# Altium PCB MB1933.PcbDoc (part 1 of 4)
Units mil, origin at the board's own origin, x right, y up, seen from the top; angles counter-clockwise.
Board outline 2755.91 x 3937.01 mil, 4 copper layers (Top Layer, GND, POWER, Bottom Layer), stack 60.63 mil thick; 228 components, 185 nets, 918 pads, 786 vias.
Unrouted connection lines stored in the file: 160.
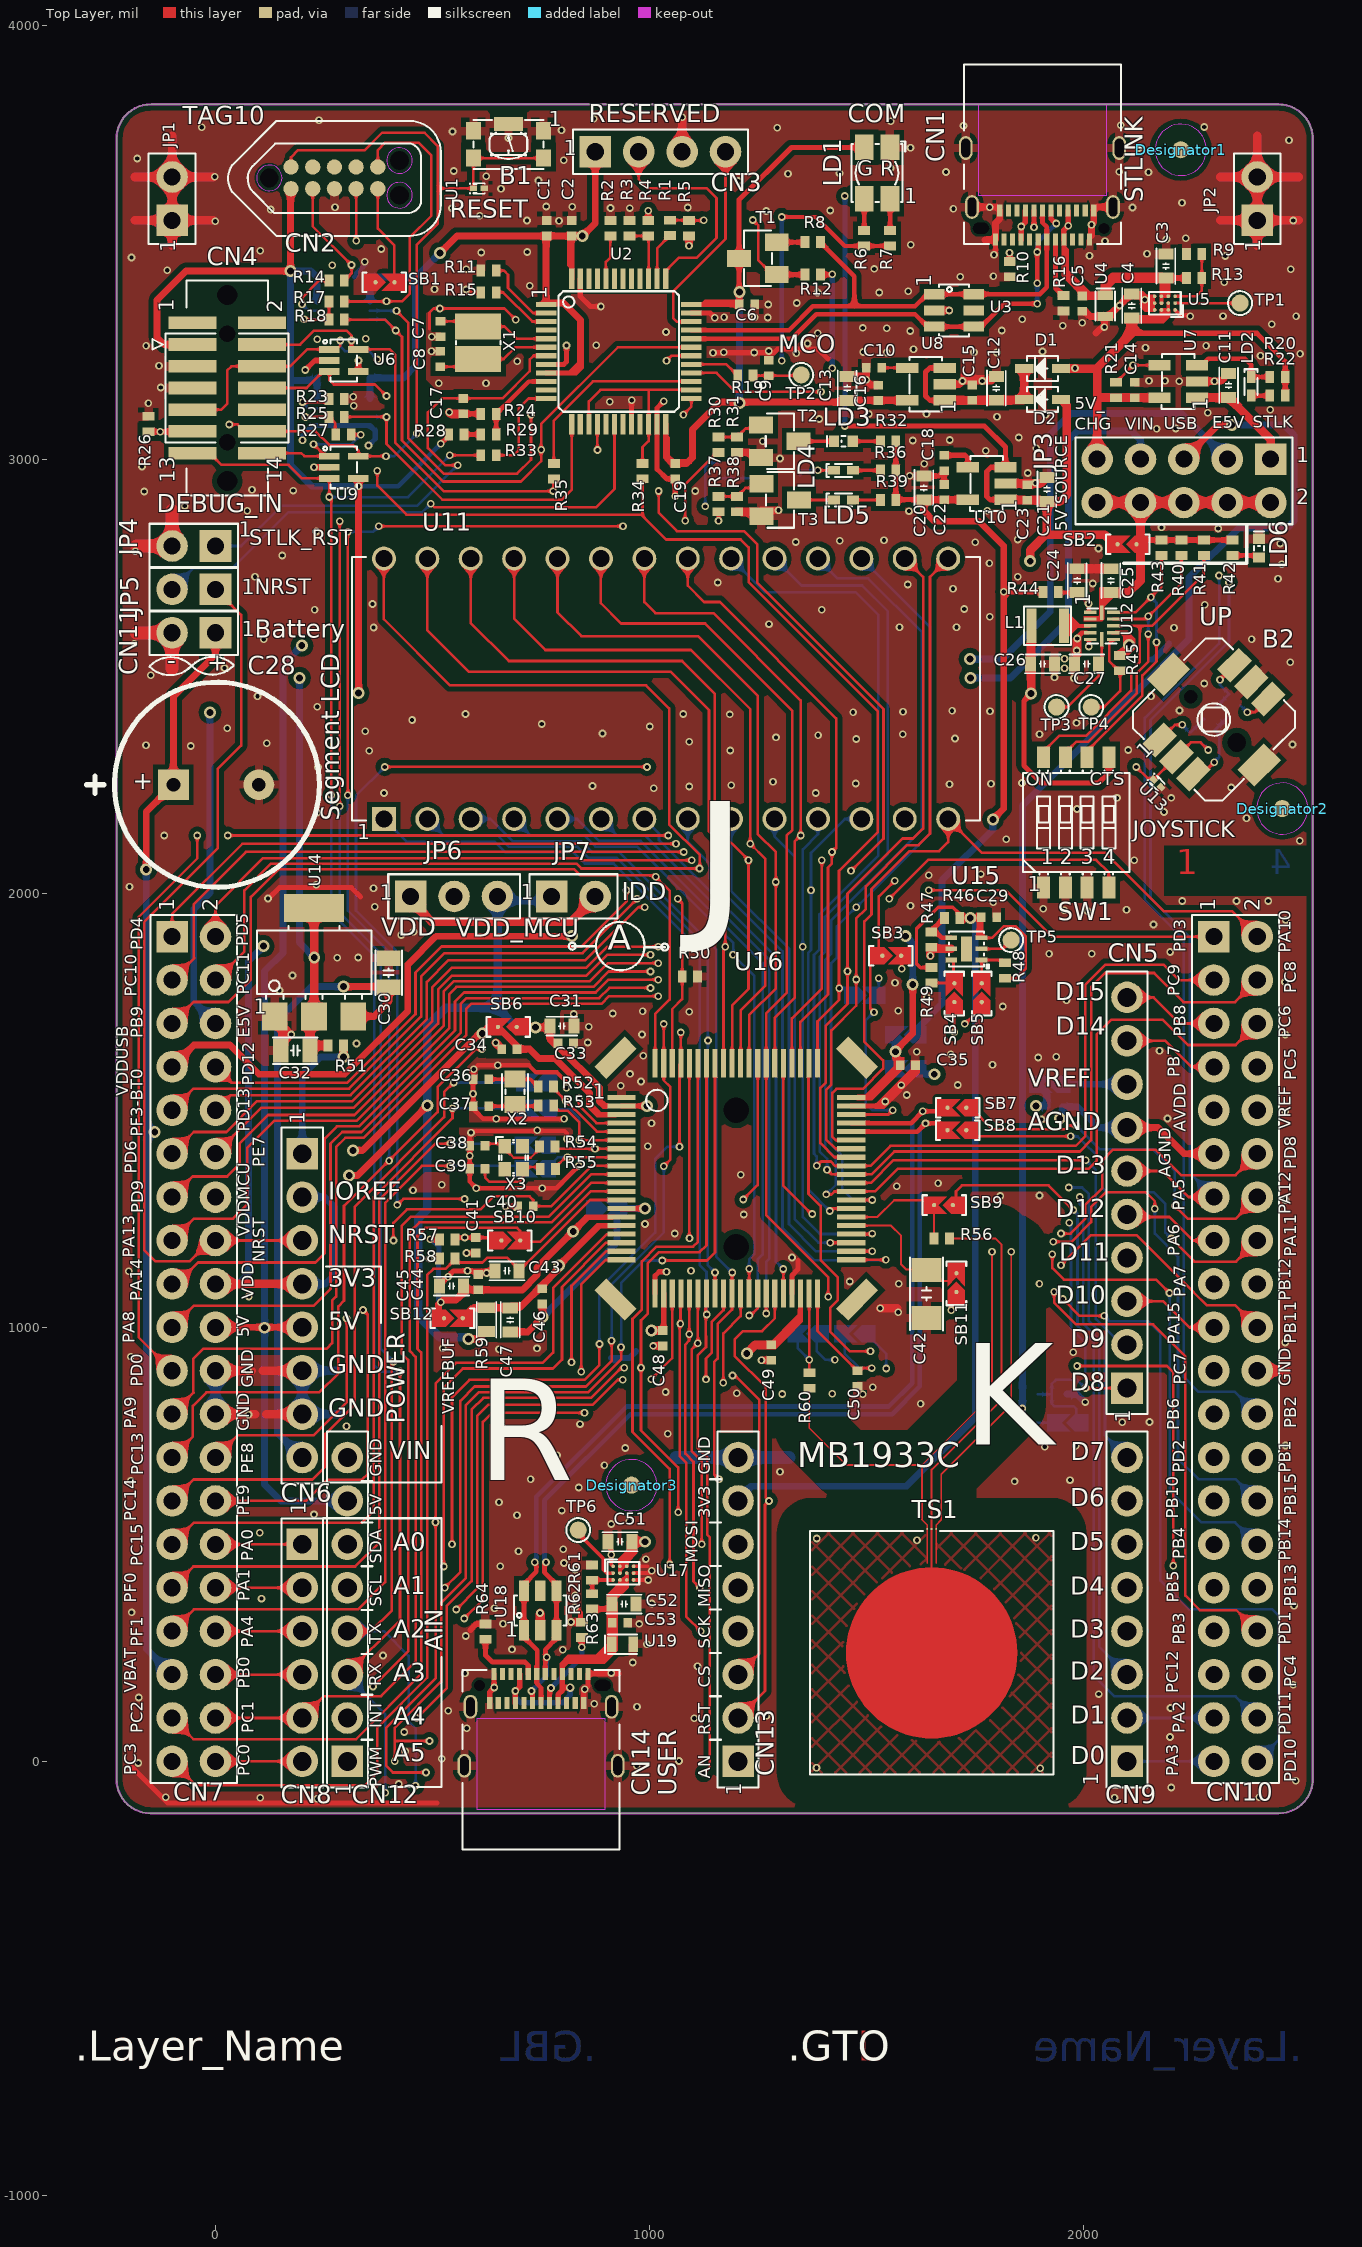
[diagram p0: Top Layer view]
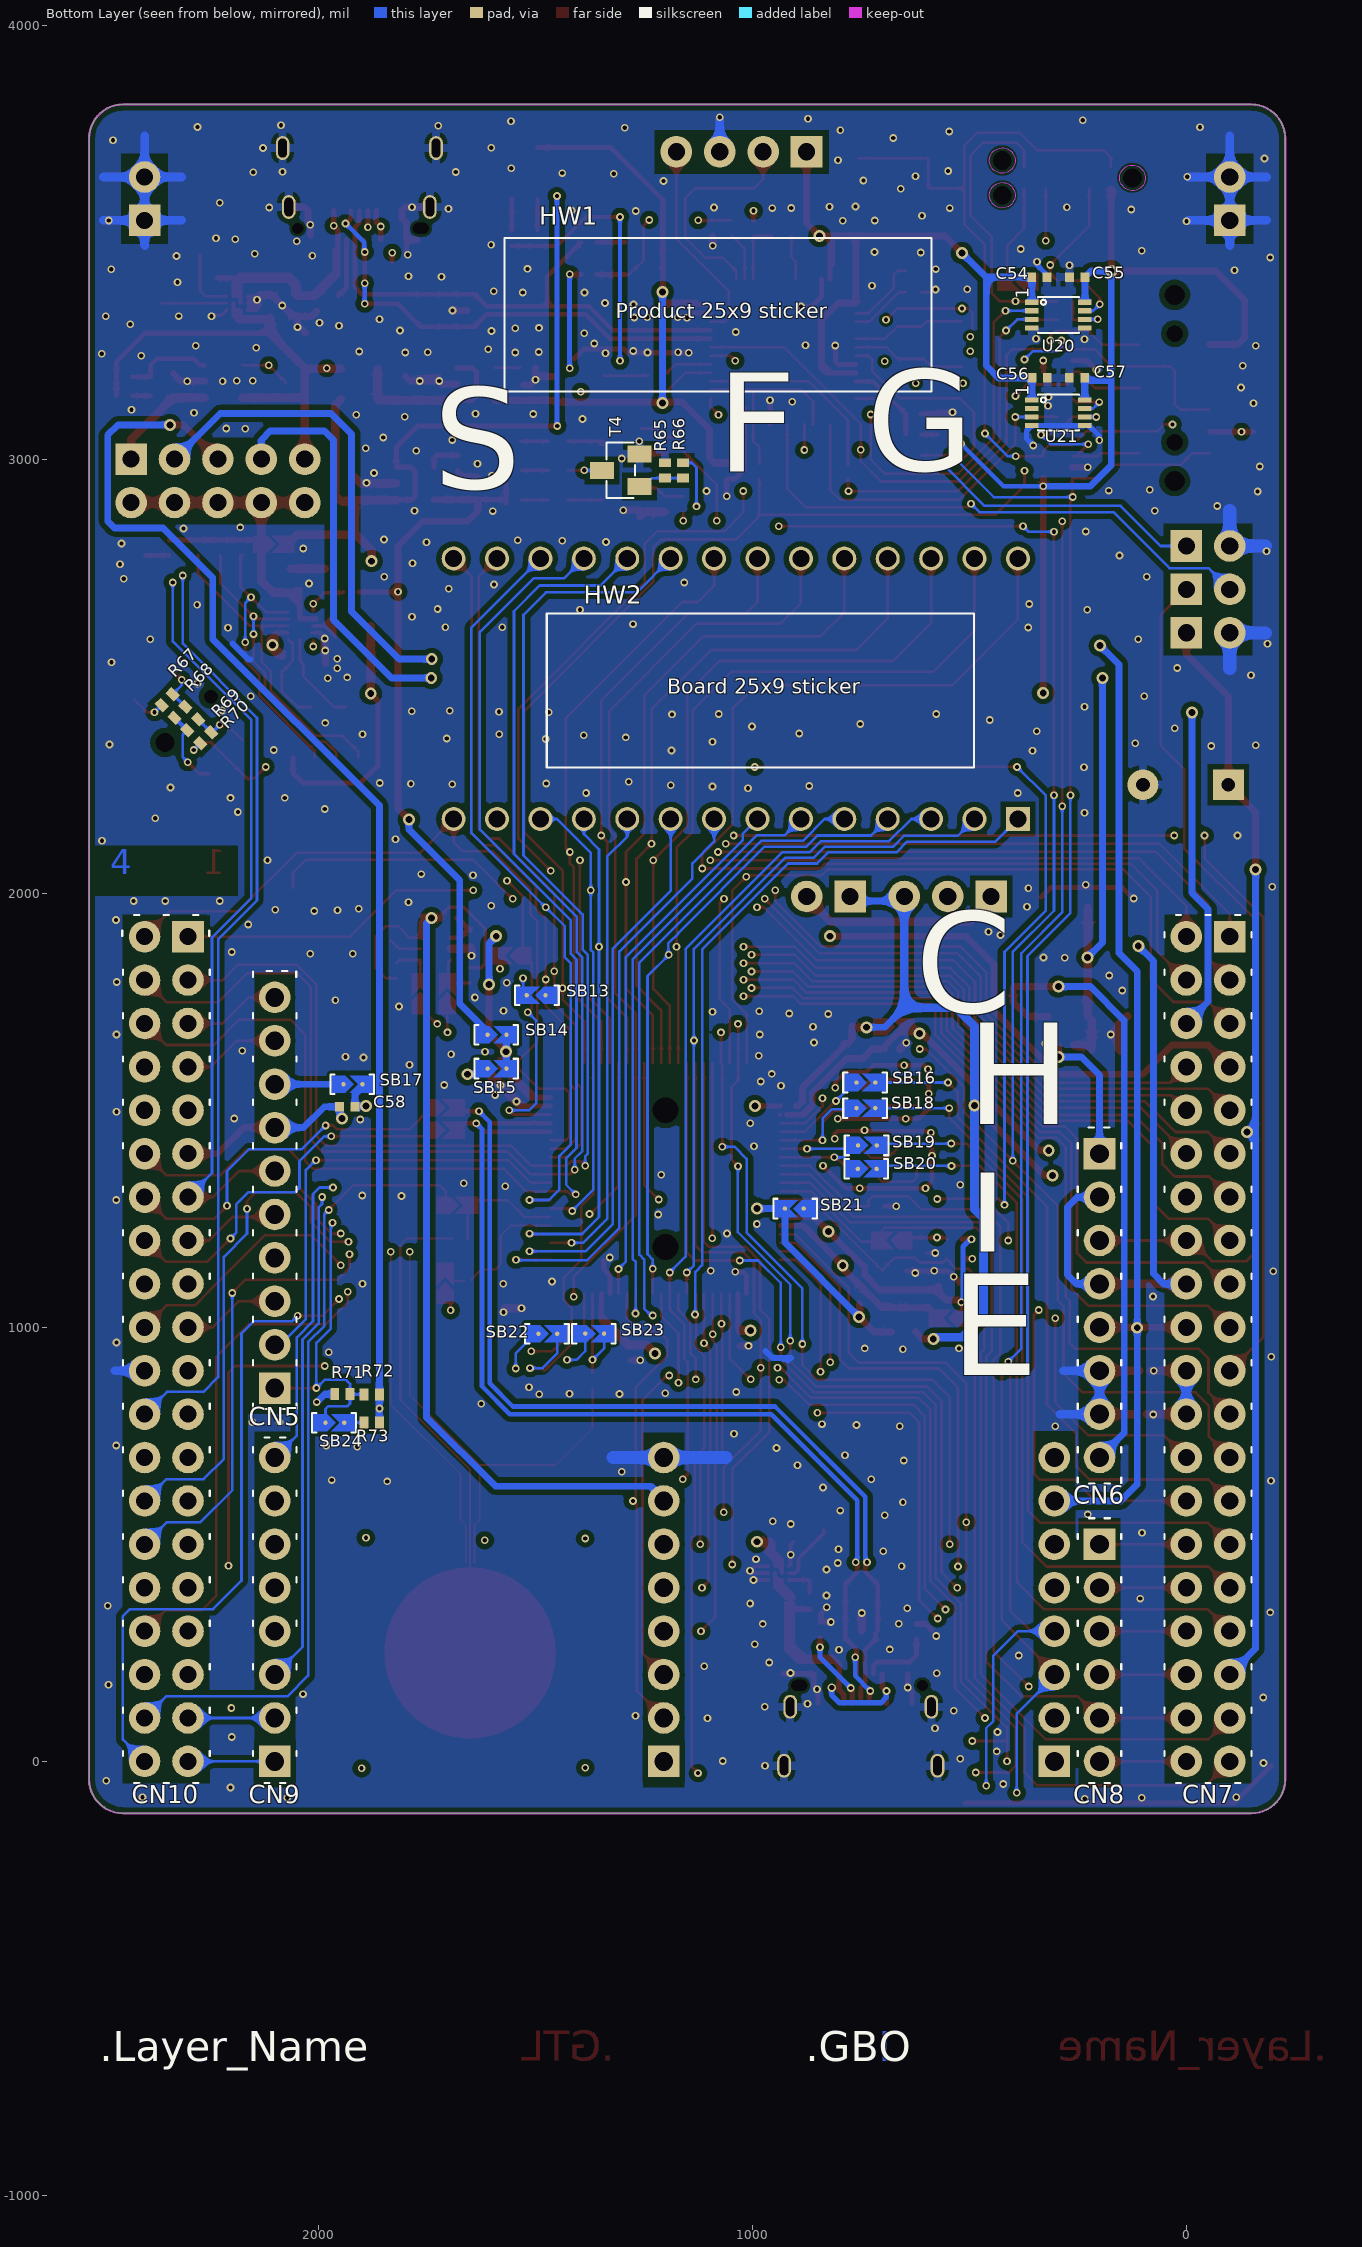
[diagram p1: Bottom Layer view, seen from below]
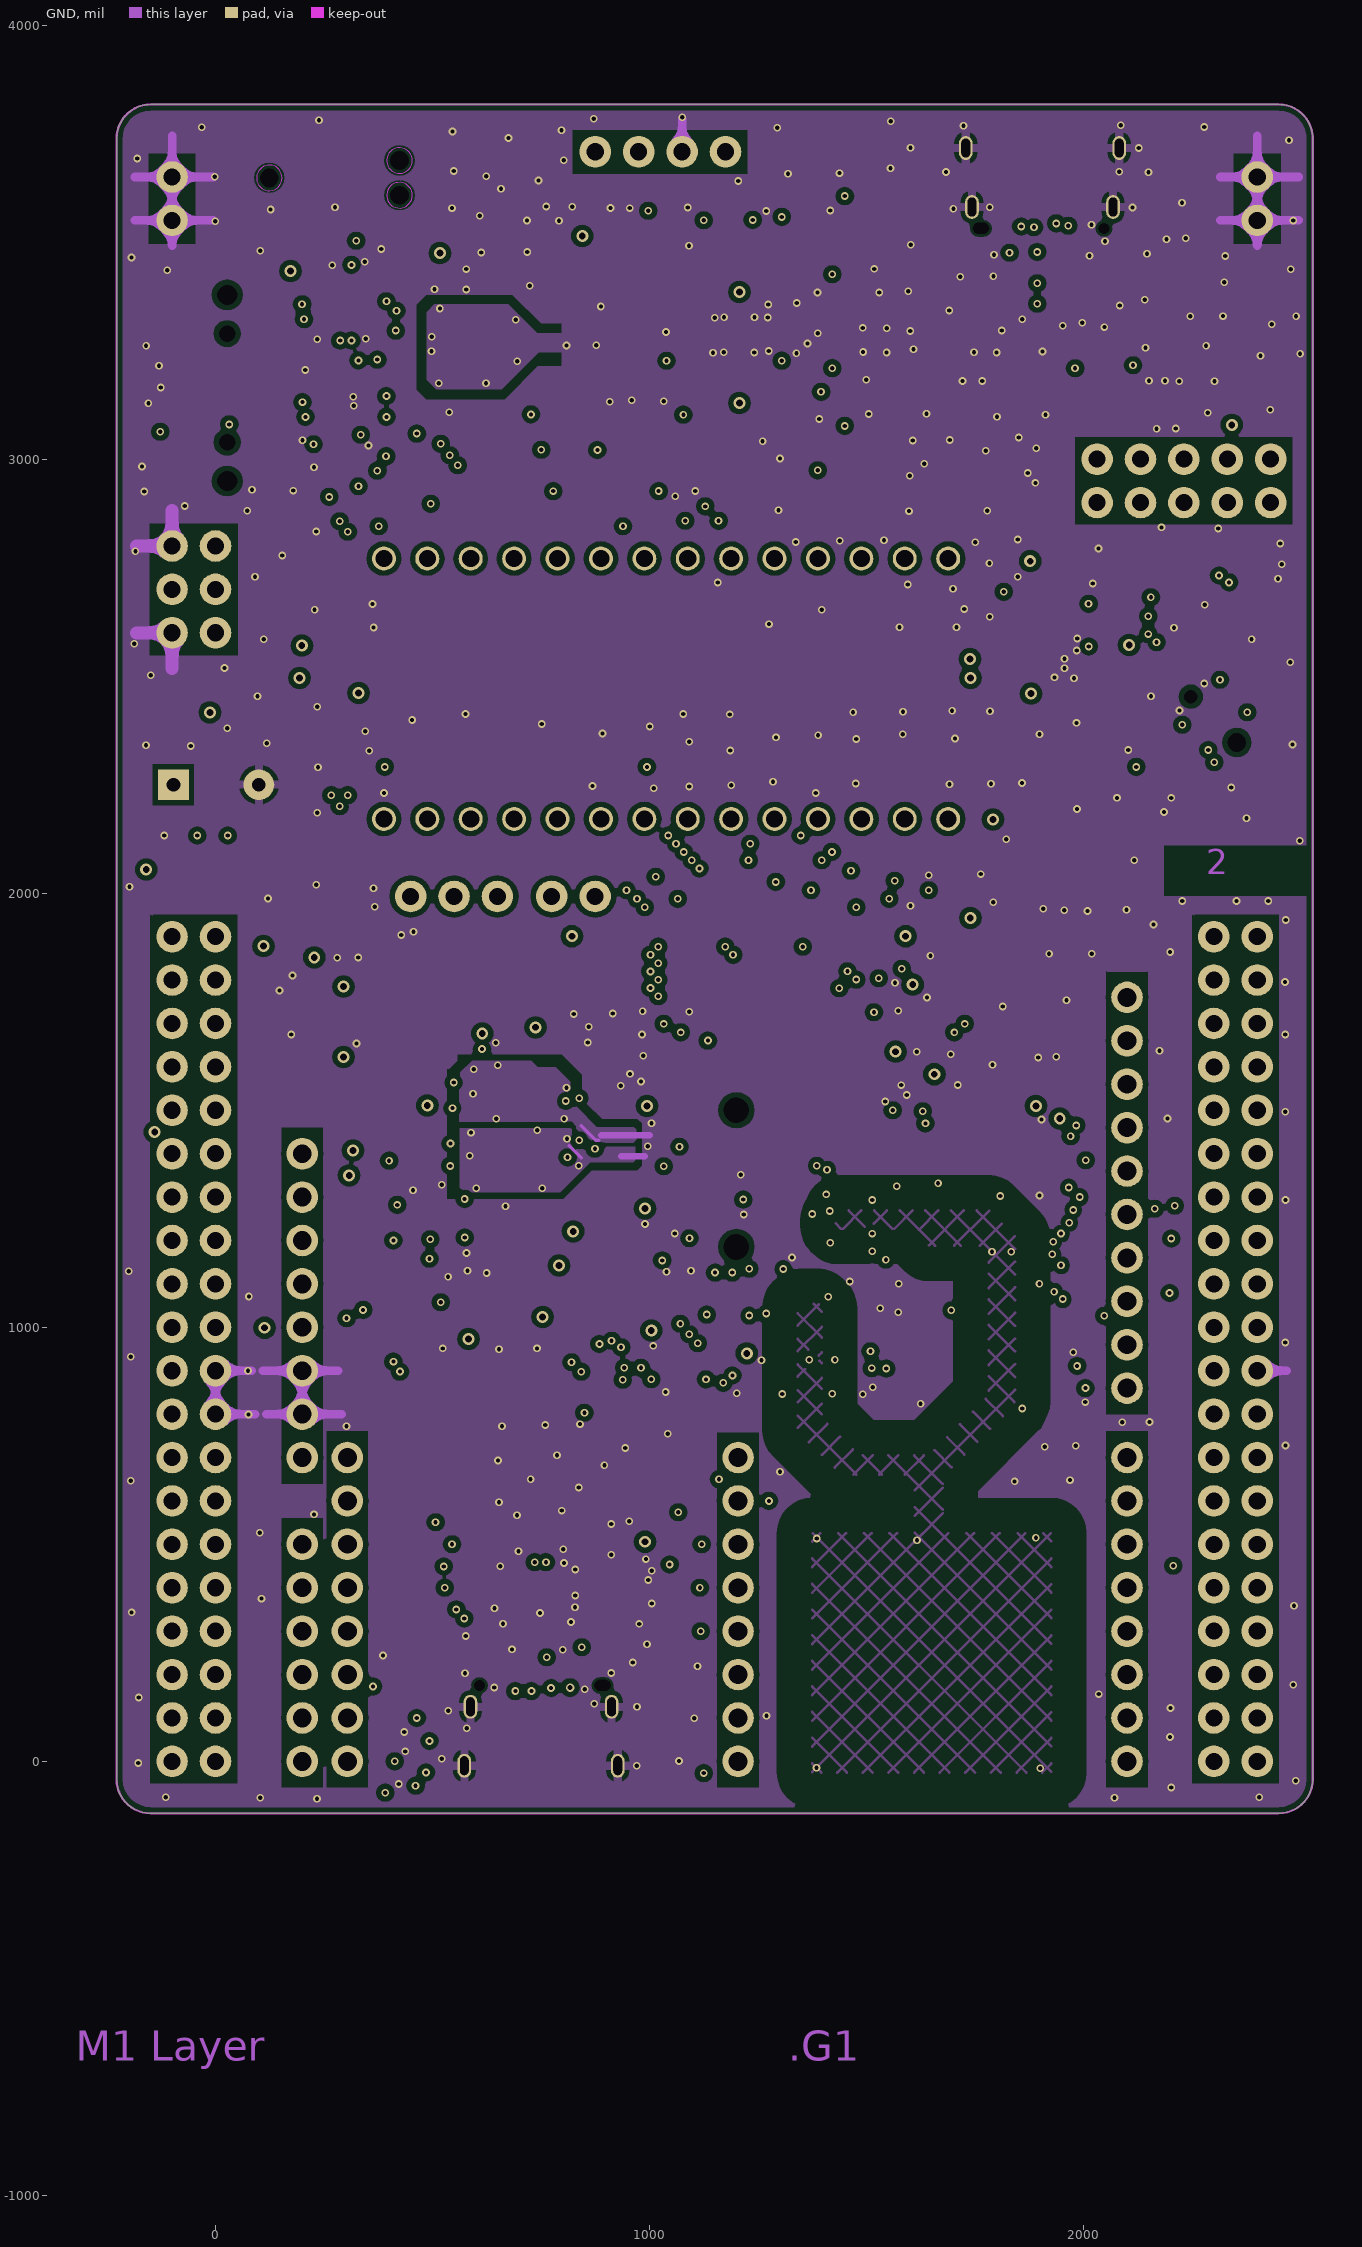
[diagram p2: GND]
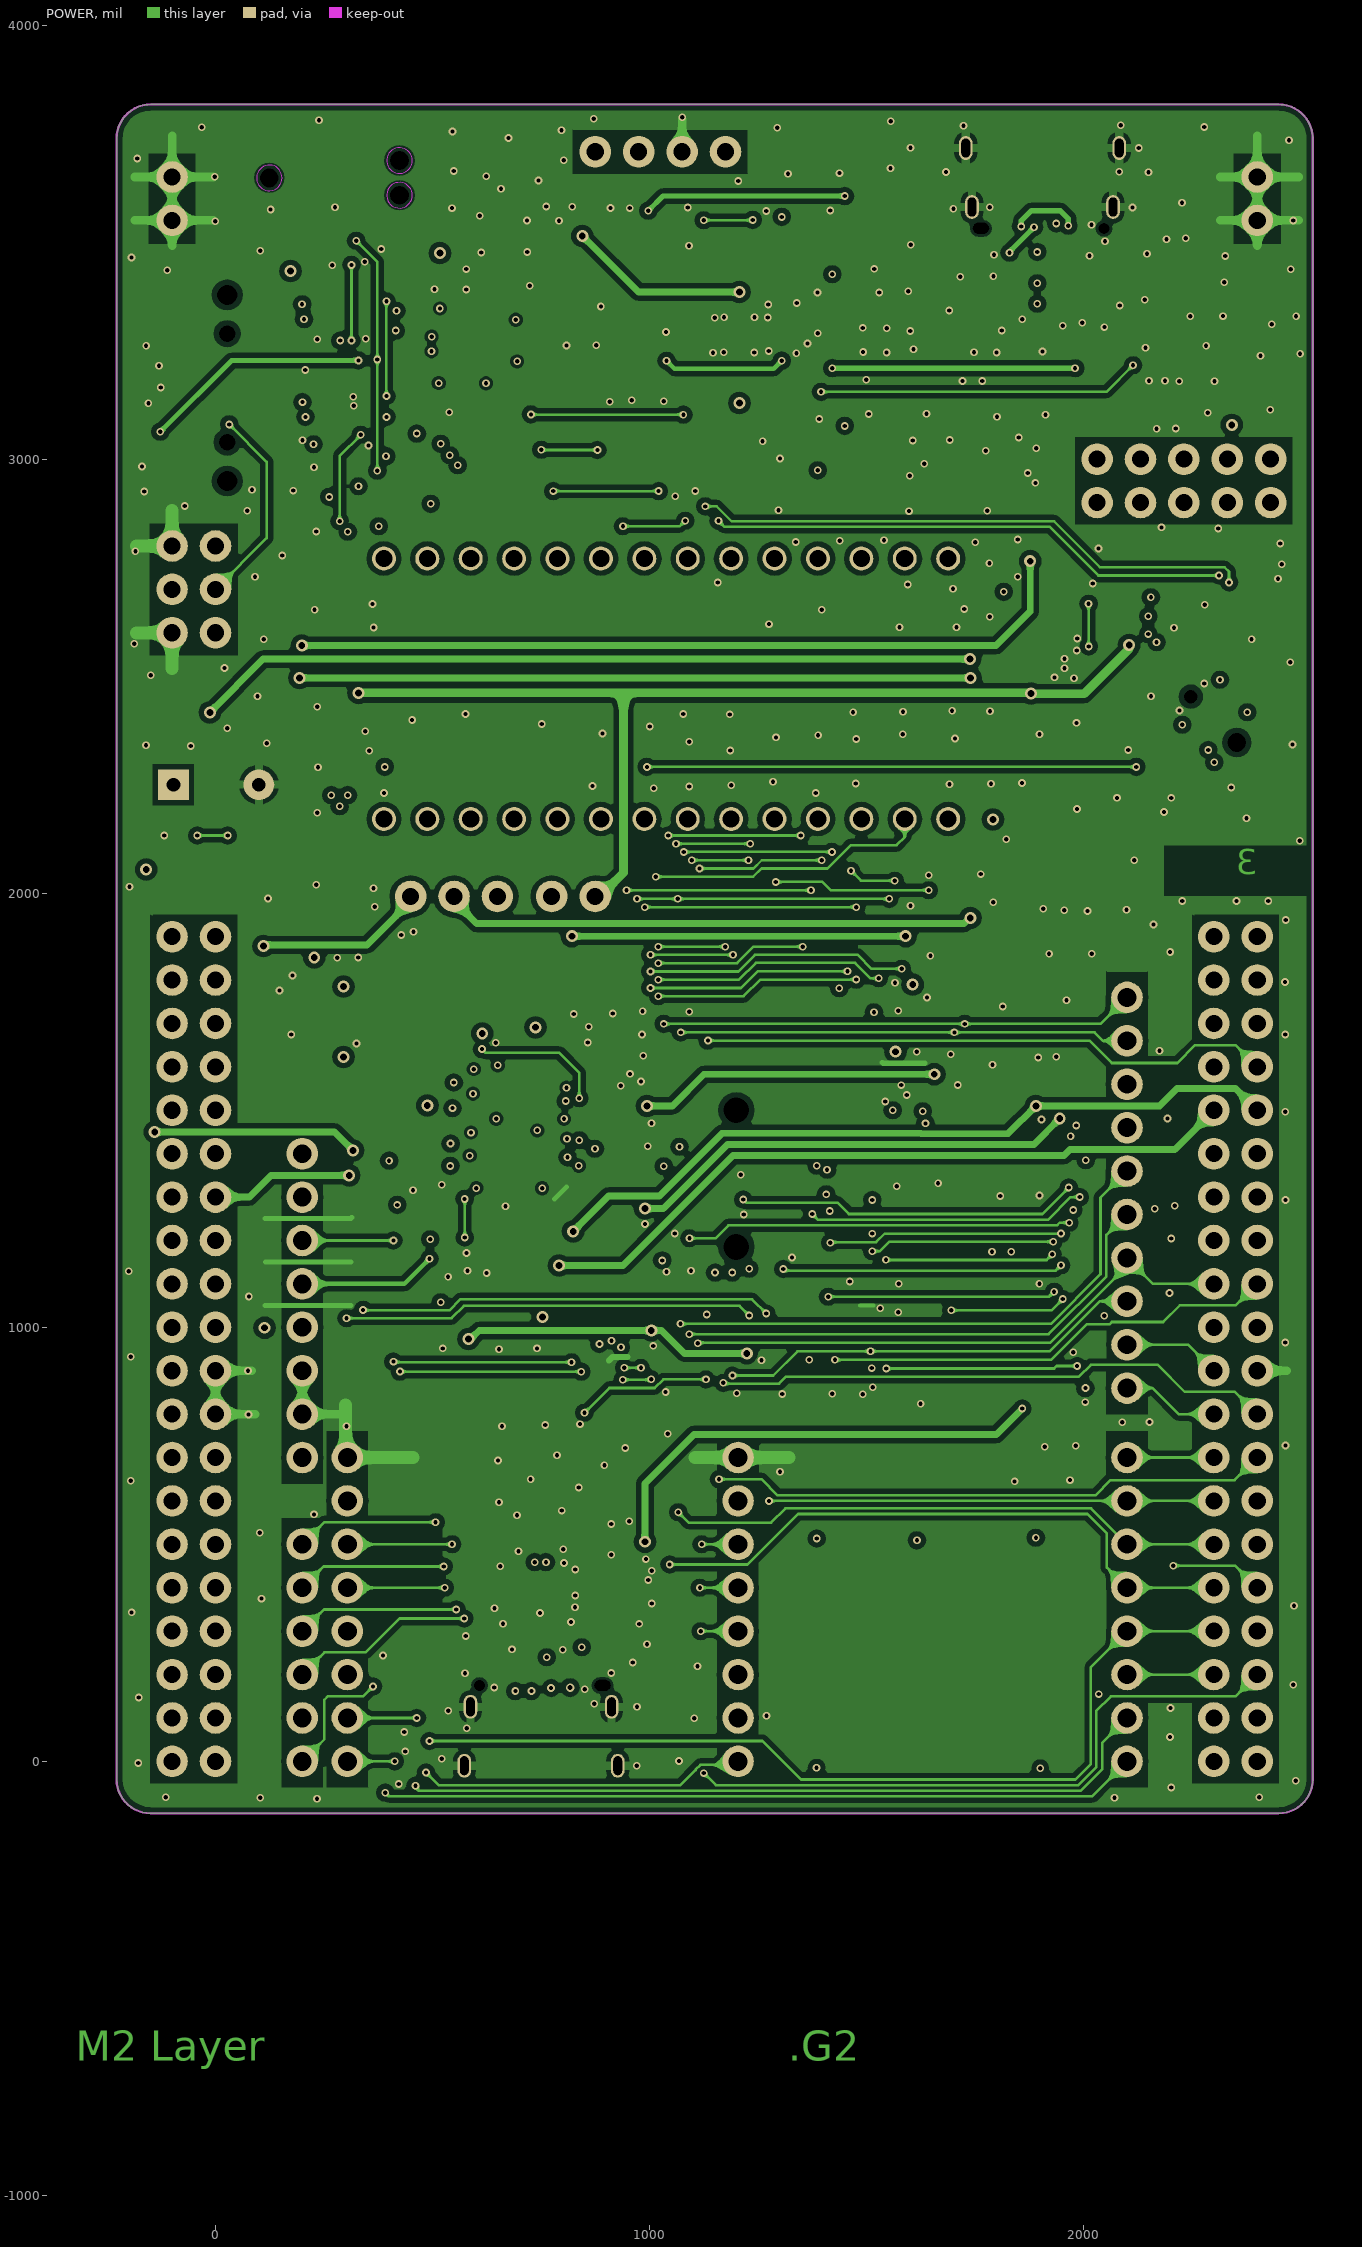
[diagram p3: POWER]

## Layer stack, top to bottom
Top Solder: solder mask 0.5909, Solder Resist, Dk 3.5
Top Layer: signal copper 1.378
Dielectric 1: core 7.874, FR-4, Dk 4.2
GND: signal copper 1.378
Dielectric 3: prepreg 39.3701, Dk 4.2
POWER: signal copper 1.378
Dielectric 2: core 7.874, Dk 4.2
Bottom Layer: signal copper 1.378
Bottom Solder: solder mask 0.5909, Solder Resist, Dk 3.5

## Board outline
-227.95,-41.01 ccw(c-149.21,-41.01) -149.21,-119.75 1681.5,-119.75 2449.22,-119.75 ccw(c2449.22,-41.01) 2527.96,-41.01 2527.96,3738.52 ccw(c2449.22,3738.52) 2449.22,3817.26 -149.21,3817.26 ccw(c-149.21,3738.52) -227.95,3738.52 -227.95,2084.98 -227.95,2084

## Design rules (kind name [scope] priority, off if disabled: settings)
Clearance CN1&CN14&U12 [InComponent('CN1')OR InComponent('CN14') OR InComponent('U12')] p1: gap=5.91 ignorepadtopadclearanceinfootprint=FALSE
Clearance Clearance_4 [InNamedPolygon('TS_SHIELD_1') vs InNet('TS_PAD')] p2: gap=5.91 ignorepadtopadclearanceinfootprint=FALSE
Clearance Clearance_3 [InNet('TS_PAD')OR InNet('TS_SHIELD') vs OnLayer('Top Layer') OR OnLayer('GND')] p3: gap=78.74 ignorepadtopadclearanceinfootprint=FALSE
Clearance CN2 [InComponent('CN2')] p4: gap=4.72 ignorepadtopadclearanceinfootprint=FALSE
Clearance Clearance_2 [InPolygon] p5: gap=11.81 ignorepadtopadclearanceinfootprint=FALSE
Clearance Clearance_1 [InNet('E5V') OR InNet('5V') OR InNet('AGND')OR InNet('VREF')  OR InNet('AVDD') OR InNet('5V_USB')  OR InNet('VDDUSB')OR InNet('VDD') OR InNet('VBAT') OR InNet('VDD_MCU') OR InNet('5V_USB') vs InComponent('CN10')OR InComponent('CN9')OR InComponent('CN5') OR InComponent('CN11') OR InComponent('CN7')OR InComponent('CN6') OR InComponent('JP4')  OR InComponent('CN14')] p6: gap=5.71 ignorepadtopadclearanceinfootprint=FALSE
Clearance KEEPOUT [OnLayer('M1-Board Shape') OR OnLayer('Keep-Out Layer')] p7: gap=15.75 ignorepadtopadclearanceinfootprint=FALSE
Clearance SB [(HasFootprint('SOLDER-BRIDGE_R0603-0R'))] p8: gap=6 ignorepadtopadclearanceinfootprint=FALSE
Clearance USB [InDifferentialPair('STLK_USB')OR InDifferentialPair('USB_CN')] p9: gap=7.87 ignorepadtopadclearanceinfootprint=FALSE
Clearance VIA&VIA [IsVia vs ISVIA] p10: gap=7.87 ignorepadtopadclearanceinfootprint=FALSE
Clearance X3 [(HasFootprint('CRY_NX1612SA_4P'))] p11: gap=5 ignorepadtopadclearanceinfootprint=FALSE
Clearance [All] p12: gap=7 ignorepadtopadclearanceinfootprint=FALSE
ComponentClearance [All] p1: gap=7.87 collisioncheckmode=3 verticalgap=7.87 showdistances=FALSE
DiffPairsRouting [All] p1: maxlimit=20 minlimit=7.87 mostfreqgap=7.87 toplayer_minwidth=10.63 toplayer_maxwidth=10.63 toplayer_prefwidth=10.63 midlayer1_minwidth=10.63 midlayer1_maxwidth=10.63 midlayer1_prefwidth=10.63 midlayer2_minwidth=10.63 midlayer2_maxwidth=10.63 midlayer2_prefwidth=10.63 bottomlayer_minwidth=10.63 bottomlayer_maxwidth=10.63 bottomlayer_prefwidth=10.63 maxuncoupledlength=500
HoleSize [All] p1: absolutevalues=TRUE maxlimit=150 minlimit=1 maxpercent=80.000 minpercent=20.000
MaxMinImpedance "Schematic Impedance Constraint_5" [InNet('PA11')] p1: minimum=85.00 maximum=95.00
MaxMinImpedance "Schematic Impedance Constraint_4" [InNet('PA12')] p2: minimum=85.00 maximum=95.00
MaxMinImpedance "Schematic Impedance Constraint_2" [InNet('STLK_USB_P')] p3: minimum=85.00 maximum=95.00
MaxMinImpedance "Schematic Impedance Constraint_1" [InNet('STLK_USB_N')] p4: minimum=85.00 maximum=95.00
MinimumSolderMaskSliver [All] p1: minsoldermaskwidth=0
PolygonConnect VIA [IsVia] p1: connectstyle=Direct reliefconductorwidth=10 reliefentries=4 polygonreliefangle="90 Angle" airgapwidth=10
PolygonConnect [All] p2: connectstyle=Relief reliefconductorwidth=19.68 reliefentries=4 polygonreliefangle="90 Angle" airgapwidth=10
RoutingVias [All] p1: holewidth=8 width=15 viastyle="Through Hole" minholewidth=8 minwidth=15 maxholewidth=28 maxwidth=50
SilkToSilkClearance [All] p1: silktosilkclearance=4
SilkToSolderMaskClearance [IsPad] p1: minsilkscreentomaskgap=0.5 clearancetoexposedcopper=TRUE
SolderMaskExpansion [All] p1: expansion=4 istentingtop=FALSE
Width [All] p1: maxlimit=30 minlimit=3 preferedwidth=8
24 further rules are at their usual default settings.

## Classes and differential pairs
component class U_USB-C_Device: C51 C52 C53 CN14 R61 R62 R63 R64 R71 R72 R73 SB24 TP6 U17 U18 U19
component class U_STM32_microcontroller_power: C28 C31 C33 C34 C35 C44 C45 C46 C47 C48 C49 CN11 R59 SB6 SB12 SB14 SB15 SB21
component class U_Segment_LCD: HW9 U11
component class U_PERIPHERAL: B2 C29 C41 C42 C50 HW10 HW11 JP6 LD3 LD4 LD5 R30 R31 R32 R36 R37 R38 R39 R46 R47 R48 R49 R56 R57 R60 R65 R66 R67 R68 R69 R70 SB10 T2 T3 T4 TP5 TS1 U13 U15
component class U_HW_Mechanical_Parts: HW1 HW2 HW3
component class U_STLINK_V2EC: C1 C2 C3 C4 C5 C6 C7 C8 C9 C10 C11 C12 C13 C14 C15 C16 C17 C19 C54 C55 C56 C57 CN1 CN2 CN3 CN4 D1 D2 JP4 JP5 LD1 LD2 R1 R2 R3 R4 R5 R6 R7 R8 R9 R10 R11 R12 R13 R14 R15 R16 R17 R18 R19 R20 R21 R22 R23 R24 R25 R26 R27 R28 R29 R33 R34 R35 SB1 T1 TP1 TP2 U2 U3 U4 U5 U6 U7 U8 U9 U20 U21 X1
component class U_Arduino_Mikrobus_connectors: C58 CN5 CN6 CN8 CN9 CN12 CN13 JP1 JP2 R51 SB17
component class U_STM32_microcontroller_IOs: B1 C36 C37 C38 C39 C40 C43 CN7 CN10 HW6 HW7 HW8 HW9 R50 R52 R53 R54 R55 R58 SB3 SB4 SB5 SB7 SB8 SB9 SB11 SB13 SB16 SB18 SB19 SB20 SB22 SB23 U1 U16 X2 X3
component class U_Power: C18 C20 C21 C22 C23 C24 C25 C26 C27 C30 C32 HW12 HW13 JP3 JP7 L1 LD6 R40 R41 R42 R43 R44 R45 SB2 SW1 TP3 TP4 U10 U12 U14
differential pair STLK_USB: +STLK_USB_P -STLK_USB_N

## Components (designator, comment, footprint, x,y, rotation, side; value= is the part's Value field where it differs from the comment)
B1 "SW-PUSH-CMS_KMR2_BLACK" SWI_C&K_Y78B23110FP__ITT_KMR231GLFS 675,3725 r0 top locked value=KMR231GLFS
B2 "Joystick MT-008A_M" SWI_XIEJIA_MT-008A_6P 2300,2400 r45 top locked value=MT-008A
C1 "Capacitor" C0402 762.8,3532 r90 top value=100nF
C2 "Capacitor" C0402 821,3532 r90 top value=100nF
C3 "Capacitor" C0603 2189.73,3444.75 r90 top value=100nF
C4 "Capacitor" C0603 2110.81,3353.25 r270 top value=10uF
C5 "Capacitor" C0402 1996.96,3358.25 r270 top value=100pF
C6 "Capacitor" C0402 1224.61,3356.44 r0 top value=100nF
C7 "Capacitor" C0402 518.41,3299.84 r90 top value=10pF
C8 "Capacitor" C0402 517.82,3230.75 r90 top value=10pF
C9 "Capacitor" C0402 1274.71,3209.98 r270 top value=20pF
C10 "Capacitor" C0402 1516.98,3210.57 r0 top value=10nF
C11 "Capacitor" C0603 2333.81,3169.92 r270 top value=10uF
C12 "Capacitor" C0603 1798.96,3163.32 r270 top value=1uF
C13 "Capacitor" C0603 1455.16,3163.13 r270 top value=1uF
C14 "Capacitor" C0402 2117.86,3159.39 r270 top value=100nF
C15 "Capacitor" C0402 1743.55,3153.29 r270 top value=100nF
C16 "Capacitor" C0402 1526.72,3152.89 r270 top value=100nF
C17 "Capacitor" C0402 571.17,3122.18 r90 top value=100nF
C18 "Capacitor" C0402 1678.55,2991.18 r90 top value=10nF
C19 "Capacitor" C0402 1058.96,2972.25 r270 top value=100nF
C20 "Capacitor" C0603 1632,2933.6 r270 top value=1uF
C21 "Capacitor" C0603 1915.56,2930.35 r270 top value=1uF
C22 "Capacitor" C0402 1678.53,2924.08 r270 top value=100nF
C23 "Capacitor" C0402 1870.58,2923.17 r270 top value=100nF
C24 "Capacitor" C0603 1985,2720 r270 top value=10uF
C25 "Capacitor" C0603 2063,2720 r270 top value=10uF
C26 "Capacitor" C0603 1905.27,2528.25 r180 top value=10uF
C27 "Capacitor" C0603 2006.96,2528.25 r0 top value=10uF
C28 "Cap_POL_TANA" CPOL_TDK_B41888C5477M000_H16 -96.85,2250 r0 top locked value=470uF
C29 "Capacitor" C0402 1782,1945 r180 top value=100nF
C30 "Capacitor" C0805 398.83,1816.87 r270 top value=10uF
C31 "Capacitor" C0603_H0P8 798,1694 r180 top value=4.7uF
C32 "Capacitor" C0805 184.26,1637.54 r0 top value=10uF
C33 "Capacitor" C0402 807,1654 r180 top value=100nF
C34 "Capacitor" C0402 677,1641 r0 top value=100nF
C35 "Capacitor" C0402 1595,1604 r180 top value=100nF
C36 "Capacitor" C0402 611.62,1571.69 r0 top value=8.2pF
C37 "Capacitor" C0402 611.62,1509.58 r0 top value=8.2pF
C38 "Capacitor" C0402 603.45,1418 r0 top value=5.6pF
C39 "Capacitor" C0402 603.45,1365 r0 top value=5.6pF
C40 "Capacitor" C0402 714.28,1279.07 r0 top value=100nF
C41 "Capacitor" C0402 599.32,1189.11 r90 top value=10nF
C42 "Capacitor" C1206_H0P85 1638,1077 r270 top value=39nF
C43 "Capacitor" C0603 671.76,1129.96 r0 top value=1uF
C44 "Capacitor" C0402 605.72,1103.97 r270 top value=100nF
C45 "Capacitor" C0603 543.7,1095.12 r180 top value=1uF
C46 "Capacitor" C0402 753.26,1071.4 r90 top value=100nF
C47 "Capacitor" C0603 679,1016.94 r270 top value=1uF
C48 "Capacitor" C0402 1030.5,974.9 r90 top value=100nF
C49 "Capacitor" C0402 1280,942 r90 top value=100nF
C50 "Capacitor" C0402 1479,882.02 r270 top value=390nF
C51 "Capacitor" C0603 932,506 r0 top value=10uF
C52 "Capacitor" C0603 941.44,362.5 r0 top value=100nF
C53 "Capacitor" C0402 931.77,319 r0 top value=100pF
C54 "Capacitor" C0402 338.49,3419.35 r0 bottom value=100nF
C55 "Capacitor" C0402 251.29,3419.35 r0 bottom value=100nF
C56 "Capacitor" C0402 337.96,3187.34 r0 bottom value=100nF
C57 "Capacitor" C0402 251.96,3187.34 r0 bottom value=100nF
C58 "Capacitor" C0402 1933,1508 r180 bottom value=100nF
CN1 "USB_TYPE_C_Receptacle" CON_USB-TYPEC_AMPHENOL_12401826E412A 1905.27,3531.73 r180 top locked value=USB_C_12401826E412A
CN2 "Tag-10-C" CON_TAG-C_TC2050-IDC-NL 274,3648 r0 top locked value="Header 5x2"
CN3 "Header 4x1" CON_SAMTEC_TSW-104-07-G-S 1024.96,3708.25 r0 top locked
CN4 "Header 7x2" CON_STDC14_Receiver_MEDIUM_WITH_MIPI10_3D 27,3164 r270 top locked value="Header 5x2"
CN5 "Socket 10x1" CON_SAMTEC_SSW-110-01-X-S 2100,1310 r90 top locked
CN6 "Socket 8x1" CON_SAMTEC_SSW-108-01-X-S 200,1050 r270 top locked
CN7 "Header 20x2" CON_SAMTEC_TSW-120-09-G-D -50,950 r270 top locked
CN8 "Socket 6x1" CON_SAMTEC_SSW-106-01-X-S 200,250 r270 top locked
CN9 "Socket 8x1" CON_SAMTEC_SSW-108-01-X-S 2100,350 r90 top locked
CN10 "Header 20x2" CON_SAMTEC_TSW-120-09-G-D 2350,950 r270 top locked
CN11 "Header 2x1" CON_SAMTEC_TSW-102-07-G-S -50,2600 r180 top
CN12 "Socket 8x1" CON_SAMTEC_SSW-108-01-X-S 303.94,350 r90 top
CN13 "Socket 8x1" CON_SAMTEC_SSW-108-01-X-S 1203.94,350 r90 top
CN14 "USB_TYPE_C_Receptacle" CON_USB-TYPEC_AMPHENOL_12401826E412A 750,175 r0 top locked value=USB_C_12401826E412A
D1 "BAT60JFILM" DIO_SOD323 1905.46,3208.73 r180 top
D2 "BAT60JFILM" DIO_SOD323 1905.46,3137.73 r180 top
Designator1 "Comment" MIRE_PLACE_SMD_1MM 2224,3712.8 r0 top
Designator2 "Comment" MIRE_PLACE_SMD_1MM 2457.49,2195.07 r0 top
Designator3 "Comment" MIRE_PLACE_SMD_1MM 958.58,636.33 r0 top
HW1 "STICKER_PRODUCT" STICKER_PRODUCT_25X9 1079.19,3332.65 r180 bottom locked value="Sticker product"
HW2 "STICKER_BOARD" STICKER_BOARD_25X9 981.4,2467.06 r180 bottom locked value="Sticker board"
JP1 "Jumper_Header 2x1" CON_SAMTEC_TSW-102-09-X-S -100,3600 r90 top value="Header 2x1"
JP2 "Jumper_Header 2x1" CON_SAMTEC_TSW-102-09-X-S 2400,3600 r90 top value="Header 2x1"
JP3 "Jumper_Header 5x2 Fitted 1-2" CON_SAMTEC_TSW-105-07-X-D 2231,2950 r180 top locked value="Header 5x2"
JP4 "Jumper_Header 2x1" CON_SAMTEC_TSW-102-07-G-S -50,2800 r180 top value="Header 2x1"
JP5 "Jumper_Header 2x1 Fitted" CON_SAMTEC_TSW-102-07-G-S -50,2700 r180 top value="Header 2x1"
JP6 "Jumper_Header 3x1 Fitted 1-2" CON_SAMTEC_TSW-103-07-F-S 549.58,1992.58 r0 top value="Header 3x1"
JP7 "Jumper_Header 2x1 Fitted" CON_SAMTEC_TSW-102-07-G-S 824.58,1992.58 r0 top value="Header 2x1"
L1 "Inductor" IND_TDK_VLS252010HBX-1 1917.13,2616.28 r180 top value=2.2uH
LD1 "LED_BICOLOR" LED_BI-GR_WE-150141SV73110 1524.15,3659.18 r180 top value=Green/Red
LD2 "LED_red" LED_0402_KINGBRIGHT_KPHHS-1005SURCK_HYPER-RED_1A2K_H0P5 2385.8,3167.81 r90 top value=Red
LD3 "LED_green" "LED_0402_EVERLIGHT_16-213SYGC/S530-E3-TR8 _YELLOW-GREEN_1A2K_H0P45" 1446.69,3041.28 r0 top value=Yellow/Green
LD4 "LED_blue" LED_0402_KINGBRIGHT_KPHHS-1005QBC-D-V_BLUE_1A2K_H0P5 1446.69,2974.16 r180 top value=Blue
LD5 "LED_red" LED_0402_KINGBRIGHT_KPHHS-1005SURCK_HYPER-RED_1A2K_H0P5 1446.69,2905.94 r180 top value=Red
LD6 "LED_green" "LED_0402_EVERLIGHT_16-213SYGC/S530-E3-TR8 _YELLOW-GREEN_1A2K_H0P45" 2404,2795.02 r270 top value=Yellow/Green
R1 "Resistor" R0402 1046.9,3532.86 r270 top value=100R
R2 "Resistor" R0402 909.75,3532.03 r270 top value=100K
R3 "Resistor" R0402 954,3532 r90 top value=10K
R4 "Resistor" R0402 997,3532 r90 top value=5K1
R5 "Resistor" R0402 1091,3532 r90 top value=36K
R6 "Resistor" R0402 1494.19,3508.93 r90 top value=330R
R7 "Resistor" R0402 1554.19,3508.93 r270 top value=1K
R8 "Resistor" R0402 1376,3500 r180 top value=1K5
R9 "Resistor" R0402 2254.59,3472.31 r0 top value=180K
R10 "Resistor" R0402 1829.83,3437.64 r270 top value=5K1
R11 "Resistor" R0402 629,3434.38 r180 top value=10K
R12 "Resistor" R0402 1376,3425 r0 top value=10K
R13 "Resistor" R0402 2254.59,3417.29 r180 top value=680K
R14 "Resistor" R0402 279.23,3411.25 r0 top value=33R
R15 "Resistor" R0402 629,3384.38 r180 top value=10K
R16 "Resistor" R0402 1953.31,3359.22 r270 top value=5K1
R17 "Resistor" R0402 279.23,3363.25 r0 top value=33R
R18 "Resistor" R0402 279.23,3321.34 r180 top value=0R
R19 "Resistor" R0402 1220.6,3192.55 r0 top value=100R
R20 "Resistor" R0402 2446.8,3189.49 r0 top value=100K
R21 "Resistor" R0402 2074.55,3159.39 r270 top value=100K
R22 "Resistor" R0402 2446.8,3146.49 r0 top value=1K
R23 "Resistor" R0402 279.23,3138.32 r0 top value=0R
R24 "Resistor" R0402 629,3104.3 r180 top value=10K
R25 "Resistor" R0402 279.23,3097.58 r180 top value=0R
R26 "Resistor" R0402 -154.42,3081.04 r270 top value=100R
R27 "Resistor" R0402 294.89,3057.22 r0 top value=33R
R28 "Resistor" R0402 555,3057 r180 top value=0R
R29 "Resistor" R0402 629,3056.65 r180 top value=10K
R30 "Resistor" R0402 1159.36,3033.3 r90 top value=47K
R31 "Resistor" R0402 1201.29,3033.3 r90 top value=100K
R32 "Resistor" R0402 1549.61,3041.28 r0 top value=270R
R33 "Resistor" R0402 629,3009 r180 top value=33R
R34 "Resistor" R0402 983.77,2972.28 r270 top value=33R
R35 "Resistor" R0402 779.41,2972.25 r270 top value=33R
R36 "Resistor" R0402 1549.61,2974.16 r0 top value=360R
R37 "Resistor" R0402 1159.35,2896.4 r90 top value=47K
R38 "Resistor" R0402 1201.28,2896.4 r90 top value=100K
R39 "Resistor" R0402 1549.61,2905.94 r0 top value=360R
R40 "Resistor" R0402 2225,2796 r270 top value=1M
R41 "Resistor" R0402 2277,2796 r270 top value=1M
R42 "Resistor" R0402 2343,2796 r270 top value=680R
R43 "Resistor" R0402 2179,2796 r270 top value=1M
R44 "Resistor" R0402 1924,2694.28 r0 top value=0R
R45 "Resistor" R0402 2084,2530 r270 top value=1M
R46 "Resistor" R0402 1697,1943 r0 top value=100K
R47 "Resistor" R0402 1649,1893 r90 top value=100K
R48 "Resistor" R0402 1819,1822.09 r270 top value=4K7
R49 "Resistor" R0402 1650,1811 r90 top value=4K7
R50 "Resistor" R0402 1093,1808 r0 top value=100K
R51 "Resistor" R0402 277.17,1649.15 r0 top value=1K
R52 "Resistor" R0402 761.23,1554.27 r0 top value=0R
R53 "Resistor" R0402 761.47,1510.83 r0 top value=0R
R54 "Resistor" R0402 764.28,1417.07 r0 top value=0R
R55 "Resistor" R0402 765.85,1364.21 r0 top value=0R
R56 "Resistor" R0402 1673.24,1204.96 r0 top value=10K
R57 "Resistor" R0402 533.87,1202.79 r0 top value=2K
R58 "Resistor" R0402 533.87,1158.6 r0 top value=0R
R59 "Resistor" R0603 624.37,1017.53 r90 top value=0R
R60 "Resistor" R0402 1368,877.28 r270 top value=1K
R61 "Resistor" R0402 867.78,434.72 r270 top value=180K
R62 "Resistor" R0402 867.78,368.72 r270 top value=680K
R63 "Resistor" R0402 844,303 r90 top value=5K1
R64 "Resistor" R0402 622,299 r90 top value=5K1
R65 "Resistor" R0402 1201.28,2974.16 r270 bottom value=100K
R66 "Resistor" R0402 1159.35,2974.16 r270 bottom value=47K
R67 "Resistor" R0402 2347.94,2446 r315 bottom value=5K1
R68 "Resistor" R0402 2318.49,2417 r135 bottom value=1K8
R69 "Resistor" R0402 2289,2388 r315 bottom value=820R
R70 "Resistor" R0402 2259,2358 r135 bottom value=510R
R71 "Resistor" R0402 1944.28,846 r180 bottom value=82K
R72 "Resistor" R0402 1876.7,845.6 r180 bottom value=100K
R73 "Resistor" R0402 1876.7,780.3 r180 bottom value=47K
SB1 "SB_ON" SOLDER-BRIDGE_R0603-0R 388.59,3407.52 r0 top value=0R
SB2 "SB_ON" SOLDER-BRIDGE_R0603-0R 2102,2804 r180 top value=0R
SB3 "SB_OFF" SOLDER-BRIDGE_R0603-0R 1556,1856 r0 top value=0R
SB4 "SB_ON" SOLDER-BRIDGE_R0603-0R 1702.28,1768.94 r90 top value=0R
SB5 "SB_ON" SOLDER-BRIDGE_R0603-0R 1765.32,1768.9 r90 top value=0R
SB6 "SB_ON" SOLDER-BRIDGE_R0603-0R 674.32,1692 r180 top value=0R
SB7 "SB_OFF" SOLDER-BRIDGE_R0603-0R 1710.08,1505.93 r180 top value=0R
SB8 "SB_OFF" SOLDER-BRIDGE_R0603-0R 1710,1454.17 r180 top value=0R
SB9 "SB_OFF" SOLDER-BRIDGE_R0603-0R 1679.08,1281.61 r180 top value=0R
SB10 "SB_ON" SOLDER-BRIDGE_R0603-0R 678.35,1200.04 r0 top value=0R
SB11 "SB_OFF" SOLDER-BRIDGE_R0603-0R 1707,1101 r90 top value=0R
SB12 "SB_ON" SOLDER-BRIDGE_R0603-0R 546,1021 r0 top value=0R
SB13 "SB_OFF" SOLDER-BRIDGE_R0603-0R 1496,1765 r0 bottom value=0R
SB14 "SB_ON" SOLDER-BRIDGE_R0603-0R 1590,1674 r180 bottom value=0R
SB15 "SB_ON" SOLDER-BRIDGE_R0603-0R 1590,1596 r180 bottom value=0R
SB16 "SB_OFF" SOLDER-BRIDGE_R0603-0R 740.16,1563.92 r180 bottom value=0R
SB17 "SB_ON" SOLDER-BRIDGE_R0603-0R 1921.86,1560 r180 bottom value=0R
SB18 "SB_OFF" SOLDER-BRIDGE_R0603-0R 740.16,1504.92 r180 bottom value=0R
SB19 "SB_ON" SOLDER-BRIDGE_R0603-0R 736.71,1419.05 r180 bottom value=0R
SB20 "SB_ON" SOLDER-BRIDGE_R0603-0R 737.11,1365 r180 bottom value=0R
SB21 "SB_ON" SOLDER-BRIDGE_R0603-0R 901.29,1273.56 r0 bottom value=0R
SB22 "SB_OFF" SOLDER-BRIDGE_R0603-0R 1473,985 r180 bottom value=0R
SB23 "SB_OFF" SOLDER-BRIDGE_R0603-0R 1365.1,985.47 r180 bottom value=0R
SB24 "SB_ON" SOLDER-BRIDGE_R0603-0R 1963.6,780.3 r180 bottom value=0R
SW1 "SWITCH_4WAY" SWI_CTS_CTS218-4LP 1983,2163 r0 top value=CT218-4LPSTRI
T1 "9013-SOT23" NPN_SOT23 1249.68,3462.41 r90 top value="NPN SOT23"
T2 "9013-SOT23" NPN_SOT23 1300.14,3041.28 r270 top value="NPN SOT23"
T3 "9013-SOT23" NPN_SOT23 1300.79,2905.94 r270 top value="NPN SOT23"
T4 "9013-SOT23" NPN_SOT23 1302.96,2974.16 r90 bottom value="NPN SOT23"
TP1 "Test Point" TP_SMD_1MM 2360.4,3359.51 r90 top value="Test Point 1mm"
TP2 "Test Point" TP_SMD_1MM 1349.52,3194.13 r90 top value="Test Point 1mm"
TP3 "Test Point" TP_SMD_1MM 1937.8,2429 r90 top value="Test Point 1mm"
TP4 "Test Point" TP_SMD_1MM 2017.6,2429 r90 top value="Test Point 1mm"
TP5 "Test Point" TP_SMD_1MM 1833,1892 r180 top value="Test Point 1mm"
TP6 "Test Point" TP_SMD_1MM 835.7,532.9 r90 top value="Test Point 1mm"
TS1 "TS_PAD" TSB_TOUCH-SENSING-BUTTON_TS-PAD-10_SHIELD-14 1650,250 r180 top locked
U1 "ESD-TRANSIL" ESD_ST0201 607,3623.76 r0 top value=ESDALC6V1-1U2
U2 "STLINK-V2EC_Old" ICC_LQFP48_7X7_P050 929,3248 r270 top locked value=STM32F103CBT6
U3 "USBLC6-2SC6" ESD_SOT23-6L 1701.73,3342.75 r270 top
U4 "ESD-TRANSIL" ESD_QFN1610_2N_1K_2A 2049.96,3353.25 r270 top value=ESDA25P35-1U1M
U5 "FPF3380UCX" ICC_WLCSP12_1P858x1P318_P040 2187.17,3359.51 r180 top
U6 "ESDALC6V1W5" ESD_SOT323-5L 295.96,3227.25 r270 top
U7 "STMPS2141STR" MOS_SOT23-5L 2217.86,3178.97 r90 top
U8 "LDK120M33R" REG_SOT23-5L 1636.76,3172.87 r90 top
U9 "ESDALC6V1W5" ESD_SOT323-5L 295.96,2981.25 r270 top
U10 "LDK120M33R" REG_SOT23-5L 1776.53,2944.08 r90 top
U11 "GH08172" LCD_DISPLAY_GH08172_DIP28 1038,2471 r0 top locked
U12 "ST1PS03" ICC_TQFN12_2X1P7_P040 2042,2616 r270 top locked value=ST1PS03AQTR
U13 "ESD-TRANSIL" ESD_ST0201 2170,2253 r315 top value=ESDALC6V1-1U2
U14 "LD1117S50TR" REG_SOT223-TAB 227.07,1841.18 r0 top
U15 "STTS22H" ICC_UDFN6-EPAD_2X2_P065 1730.08,1871.69 r90 top
U16 "STM32U083MCT6" ICC_LQFP80_12X12_P050_SOCKET_YAMAICHI_IC149-080-130-B5 1200,1342.52 r270 top locked
U17 "AW329xxFCR" ICC_WLCSP12_1P858x1P318_P040 939.65,433.75 r0 top locked value=FPF3380UCX
U18 "USBLC6-2SC6" ESD_SOT23-6L 748.18,347.28 r0 top
U19 "ESD-TRANSIL" ESD_QFN1610_2N_1K_2A 937.51,270 r0 top value=ESDA25P35-1U1M
U20 "SN74LVC2T45DCUT" ICC_VSSOP8_DCU_R-PDSO-G8_2X2P30_P050 294.98,3332 r270 bottom
U21 "SN74LVC2T45DCUT" ICC_VSSOP8_DCU_R-PDSO-G8_2X2P30_P050 294.98,3107.14 r270 bottom
X1 "XTAL_2_PINS" CRY_NX3225GD_2P 605.13,3268.15 r90 top value=8MHz
X2 "XTAL_2_PINS" CRY_NX2012SA_2P 689.97,1542.36 r90 top value=32.768KHz
X3 "XTAL_4_PINS" CRY_NX2016SA_4P 686.92,1390.49 r270 top value=24MHz

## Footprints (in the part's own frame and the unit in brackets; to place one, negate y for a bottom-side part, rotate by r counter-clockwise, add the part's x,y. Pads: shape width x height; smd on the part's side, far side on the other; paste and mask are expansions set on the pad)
C0402 [mm]
  rect 0.51x0.56 smd mask+0.05: 1(-0.45,0) 2(0.45,0)
  body extent -0.5,-0.3 0.5,0.3, height 0.4
C0603 [mm]
  rect 0.64x0.89 smd mask+0.05: 1(-0.7,0) 2(0.7,0)
  silkscreen extent -1.05,-0.55 1.02,0.55, body extent -0.9,-0.5 0.9,0.5, height 1.4
C0603_H0P8 [mm] "MCD-01540"
  rect 0.64x0.89 smd mask+0.05: 1(-0.7,0) 2(0.7,0)
  silkscreen extent -0.9,-0.55 0.9,0.55, body extent -0.9,-0.5 0.9,0.5, height 1
C0805 [mm]
  rect 0.9x1.4 smd mask+0.05: 1(-0.85,0) 2(0.85,0)
  silkscreen extent -1.3,-0.77 1.3,0.77, body extent -1.1,-0.7 1.1,0.7, height 1.35
C1206_H0P85 [mm]
  rect 1.4x1.78 smd mask+0.05: 1(-1.4,0) 2(1.4,0)
  silkscreen extent -2.12,-0.97 2.15,0.97, body extent -1.6,-0.8 1.6,0.8, height 0.95
CON_SAMTEC_SSW-106-01-X-S [mm] "MCD-02079"
  rect 1.85x1.85 / inner round 1.85 / far side rect 1.85x1.85 hole 1.1 mask+0.05: 1(-6.35,0)
  round 1.85 hole 1.1 mask+0.05: 2(-3.81,0) 3(-1.27,0) 4(1.27,0) 5(3.81,0) 6(6.35,0)
  silkscreen extent -7.88,-1.2 7.88,1.2, body extent -7.88,-1.21 7.88,1.21, height 8.51
CON_SAMTEC_SSW-108-01-X-S [mm] "MCD-01743"
  rect 1.85x1.85 / inner round 1.85 / far side rect 1.85x1.85 hole 1.1 mask+0.05: 1(-8.89,0)
  round 1.85 hole 1.1 mask+0.05: 2(-6.35,0) 3(-3.81,0) 4(-1.27,0) 5(1.27,0) 6(3.81,0) 7(6.35,0) 8(8.89,0)
  silkscreen extent -10.42,-1.2 10.42,1.2, body extent -10.42,-1.21 10.42,1.21, height 8.51
CON_SAMTEC_SSW-110-01-X-S [mm] "MCD-02080"
  rect 1.85x1.85 / inner round 1.85 / far side rect 1.85x1.85 hole 1.1 mask+0.05: 1(-11.43,0)
  round 1.85 hole 1.1 mask+0.05: 2(-8.89,0) 3(-6.35,0) 4(-3.81,0) 5(-1.27,0) 6(1.27,0) 7(3.81,0) 8(6.35,0) 9(8.89,0) 10(11.43,0)
  silkscreen extent -12.96,-1.2 12.96,1.2, body extent -12.96,-1.21 12.96,1.21, height 8.51
CON_SAMTEC_TSW-102-07-G-S [mm]
  rect 1.85x1.85 / inner round 1.85 / far side rect 1.85x1.85 hole 1 mask+0.05: 1(-1.27,0)
  round 1.85 hole 1 mask+0.05: 2(1.27,0)
  silkscreen extent -2.58,-1.3 2.58,1.3, body extent -2.67,-1.3 2.58,1.3, height 8.38
CON_SAMTEC_TSW-102-09-X-S [mm]
  rect 1.85x1.85 / inner round 1.85 / far side rect 1.85x1.85 hole 1 mask+0.05: 1(-1.27,0)
  round 1.85 hole 1 mask+0.05: 2(1.27,0)
  silkscreen extent -2.64,-1.37 2.64,1.37, body extent -2.67,-1.3 2.58,1.3, height 8.38
CON_SAMTEC_TSW-103-07-F-S [mm]
  rect 1.85x1.85 / inner round 1.85 / far side rect 1.85x1.85 hole 1 mask+0.05: 1(-2.54,0)
  round 1.85 hole 1 mask+0.05: 2(0,0) 3(2.54,0)
  silkscreen extent -3.85,-1.3 3.85,1.3, body extent -3.94,-1.37 3.91,1.37, height 8.38
CON_SAMTEC_TSW-104-07-G-S [mm]
  rect 1.85x1.85 / inner round 1.85 / far side rect 1.85x1.85 hole 1 mask+0.05: 1(-3.81,0)
  round 1.85 hole 1 mask+0.05: 2(-1.27,0) 3(1.27,0) 4(3.81,0)
  silkscreen extent -5.12,-1.3 5.12,1.3, body extent -5.21,-1.37 5.18,1.37, height 8.38
CON_SAMTEC_TSW-105-07-X-D [mm]
  rect 1.85x1.85 / inner round 1.85 / far side rect 1.85x1.85 hole 1 mask+0.05: 1(-5.08,-1.27)
  round 1.85 hole 1 mask+0.05: 2(-5.08,1.27) 3(-2.54,-1.27) 4(-2.54,1.27) 5(0,-1.27) 6(0,1.27) 7(2.54,-1.27) 8(2.54,1.27) 9(5.08,-1.27) 10(5.08,1.27)
  silkscreen extent -6.35,-2.54 6.35,2.54, body extent -6.35,-2.54 6.35,2.55, height 8.38
CON_SAMTEC_TSW-120-09-G-D [mm] "MCD-03295"
  rect 1.85x1.85 / inner round 1.85 / far side rect 1.85x1.85 hole 1 mask+0.05: 1(-24.13,-1.27)
  round 1.85 hole 1 mask+0.05: 2(-24.13,1.27) 3(-21.59,-1.27) 4(-21.59,1.27) 5(-19.05,-1.27) 6(-19.05,1.27) 7(-16.51,-1.27) 8(-16.51,1.27) 9(-13.97,-1.27) 10(-13.97,1.27) 11(-11.43,-1.27) 12(-11.43,1.27) 13(-8.89,-1.27) 14(-8.89,1.27) 15(-6.35,-1.27) 16(-6.35,1.27) 17(-3.81,-1.27) 18(-3.81,1.27) 19(-1.27,-1.27) 20(-1.27,1.27) 21(1.27,-1.27) 22(1.27,1.27) 23(3.81,-1.27) 24(3.81,1.27) 25(6.35,-1.27) 26(6.35,1.27) 27(8.89,-1.27) 28(8.89,1.27) 29(11.43,-1.27) 30(11.43,1.27) 31(13.97,-1.27) 32(13.97,1.27) 33(16.51,-1.27) 34(16.51,1.27) 35(19.05,-1.27) 36(19.05,1.27) 37(21.59,-1.27) 38(21.59,1.27) 39(24.13,-1.27) 40(24.13,1.27)
  silkscreen extent -25.4,-2.54 25.4,2.54, body extent -25.4,-2.54 25.4,2.54, height 8.38
CON_STDC14_Receiver_MEDIUM_WITH_MIPI10_3D [mm] "compatible with FTSH-105-01-L-DV,-K and FTSH-107-01-L-DV,-K,-A,-P,-ES"
  round 0 hole 1.19 unplated mask+0.05: 0(-5.445,0) 0(5.445,0)
  round 0 hole 0.97 unplated mask+0.05: 0(-3.175,0) 0(3.175,0)
  rect 0.74x2.79 smd mask+0.05: 1(-3.81,-2.032) 2(-3.81,2.032) 3(-2.54,-2.032) 4(-2.54,2.032) 5(-1.27,-2.032) 6(-1.27,2.032) 7(0,-2.032) 8(0,2.032) 9(1.27,-2.032) 10(1.27,2.032) 11(2.54,-2.032) 12(2.54,2.032) 13(3.81,-2.032) 14(3.81,2.032)
  silkscreen extent -6.3,-4.38 6.3,3.6, body extent -6.3,-2.92 6.3,2.92, height 6.6
CON_TAG-C_TC2050-IDC-NL [mm]
  round 0.9 smd paste+0 mask+0.05: 1(-2.54,-0.635) 2(-1.27,-0.635) 3(0,-0.635) 4(1.27,-0.635) 5(2.54,-0.635) 6(2.54,0.635) 7(1.27,0.635) 8(0,0.635) 9(-1.27,0.635) 10(-2.54,0.635)
  round 0 hole 1.1 unplated mask+0.05: 11(-3.81,0) 12(3.81,-1.015) 13(3.81,1.015)
  Multi-Layer keep-out circle w0.01: c-3.81,0 r0.75
  Multi-Layer keep-out circle w0.01: c3.81,1.015 r0.75
  Multi-Layer keep-out circle w0.01: c3.81,-1.015 r0.75
  silkscreen extent -6.22,-3.4 6.22,3.33, body extent -6.28,-3.46 6.28,3.39, height 13
CON_USB-TYPEC_AMPHENOL_12401826E412A [mm] "MCD-03232"
  round 0 hole 0.65 unplated mask+0.05: 0(-3.6,0)
  round 0 hole 0.65 slot 0.95 at 0 deg unplated mask+0.05: 0(3.6,0)
  rect 0.3x0.7 smd mask+0.05: A1(-2.75,0.66) A2(-2.25,0.66) A3(-1.75,0.66) A4(-1.25,0.66) A5(-0.75,0.66) A6(-0.25,0.66) A7(0.25,0.66) A8(0.75,0.66) A9(1.25,0.66) A10(1.75,0.66) A11(2.25,0.66) A12(2.75,0.66) B1(2.5,-1.04) B2(2,-1.04) B3(1.5,-1.04) B4(1,-1.04) B5(0.5,-1.04) B6(0,-1.04) B7(-0.5,-1.04) B8(-1,-1.04) B9(-1.5,-1.04) B10(-2,-1.04) B11(-2.5,-1.04) B12(-3,-1.04)
  oval 0.8x1.4 hole 0.5 slot 1.1 at 90 deg mask+0.05: SH1(-4.13,-1.25) SH2(4.13,-1.25) SH3(-4.49,-4.7) SH4(4.49,-4.7)
  Top Layer keep-out region: -3.75,-7.24 3.75,-7.24 3.75,-1.95 -3.75,-1.95
  silkscreen extent -4.6,-9.59 4.6,0.91, body extent -4.6,-9.59 4.6,0.91, height 3.25
CPOL_TDK_B41888C5477M000_H16 [mm]
  rect 1.8x1.8 hole 0.8: 1(0,0)
  round 1.8 hole 0.8: 2(5,0)
  silkscreen extent -5.09,-6 8.54,6, body extent -2.46,-5 7.54,5, height 16.8
CRY_NX2012SA_2P [mm]
  rect 1x1.25 smd mask+0.05: 1(-0.75,0) 2(0.75,0)
  silkscreen extent -1.05,-0.75 1.05,0.75, body extent -1.05,-0.63 1.05,0.63, height 0.6
CRY_NX2016SA_4P [mm]
  rect 0.85x0.75 smd mask+0.05: 1(-0.675,-0.525) 2(0.675,-0.525) 3(0.675,0.525) 4(-0.675,0.525)
  silkscreen extent -1.22,-1.02 1.05,0.85, body extent -1.05,-0.85 1.05,0.85, height 0.7
CRY_NX3225GD_2P [mm]
  rect 1.5x2.7 smd mask+0.05: 1(-0.95,0) 2(0.95,0)
  silkscreen extent -0.1,-1.3 0.1,1.3, body extent -1.65,-1.3 1.65,1.3, height 1
DIO_SOD323 [mm]
  rect 1.06x0.54 smd mask+0.05: 1(-1.07,0) 2(1.07,0)
  silkscreen extent -0.9,-0.72 0.9,0.72, body extent -1.3,-0.78 1.3,0.78, height 1.17
ESD_QFN1610_2N_1K_2A [mm] "DFN, 2-Leads, Body 1.60x1.00mm"
  rect 0.55x0.9 smd mask+0.05: 1(-0.625,0) 2(0.625,0)
  silkscreen extent -1.02,-0.58 0.85,0.58, body extent -0.85,-0.55 0.85,0.55, height 0.6
ESD_SOT23-6L [mm]
  rect 0.6x1.2 smd mask+0.05: 1(-0.95,-1.15) 2(0,-1.15) 3(0.95,-1.15) 4(0.95,1.15) 5(0,1.15) 6(-0.95,1.15)
  silkscreen extent -1.53,-0.87 1.53,0.87, body extent -1.52,-1.5 1.52,1.5, height 1.45
ESD_SOT323-5L [mm]
  rect 0.4x1.2 smd mask+0.05: 1(-0.65,-0.85) 2(0,-0.85) 3(0.65,-0.85) 4(0.65,0.85) 5(-0.65,0.85)
  silkscreen extent -1.22,-1.21 1.22,0.77, body extent -1.15,-1.05 1.15,1.05, height 1.1
ESD_ST0201 [mm]
  rect 0.425x0.33 smd mask+0.05: 1(-0.312,0) 2(0.312,0)
  silkscreen extent -0.55,-0.3 0.33,0.3, body extent -0.34,-0.18 0.34,0.18, height 0.34
ICC_LQFP48_7X7_P050 [mm]
  rect 0.3x1.2 smd mask+0.05: 1(-2.75,-4.25) 2(-2.25,-4.25) 3(-1.75,-4.25) 4(-1.25,-4.25) 5(-0.75,-4.25) 6(-0.25,-4.25) 7(0.25,-4.25) 8(0.75,-4.25) 9(1.25,-4.25) 10(1.75,-4.25) 11(2.25,-4.25) 12(2.75,-4.25) 25(2.75,4.25) 26(2.25,4.25) 27(1.75,4.25) 28(1.25,4.25) 29(0.75,4.25) 30(0.25,4.25) 31(-0.25,4.25) 32(-0.75,4.25) 33(-1.25,4.25) 34(-1.75,4.25) 35(-2.25,4.25) 36(-2.75,4.25)
  rect 1.2x0.3 smd mask+0.05: 13(4.25,-2.75) 14(4.25,-2.25) 15(4.25,-1.75) 16(4.25,-1.25) 17(4.25,-0.75) 18(4.25,-0.25) 19(4.25,0.25) 20(4.25,0.75) 21(4.25,1.25) 22(4.25,1.75) 23(4.25,2.25) 24(4.25,2.75) 37(-4.25,2.75) 38(-4.25,2.25) 39(-4.25,1.75) 40(-4.25,1.25) 41(-4.25,0.75) 42(-4.25,0.25) 43(-4.25,-0.25) 44(-4.25,-0.75) 45(-4.25,-1.25) 46(-4.25,-1.75) 47(-4.25,-2.25) 48(-4.25,-2.75)
  silkscreen extent -3.52,-3.52 3.52,3.52, body extent -4.5,-4.5 4.5,4.5, height 1.6
ICC_LQFP80_12X12_P050_SOCKET_YAMAICHI_IC149-080-130-B5 [mm] "MCD-03131"
  rect 1x2.5 smd rot 135 mask+0.05: 0(-7.071,7.071) 0(7.071,-7.071)
  rect 1x2.5 smd rot 45 mask+0.05: 0(-7.071,-7.071) 0(7.071,7.071)
  round 0 hole 1.5 unplated mask+0.05: 0(-4,0) 0(4,0)
  rect 0.3x1.65 smd mask+0.05: 1(-4.75,-6.725) 2(-4.25,-6.725) 3(-3.75,-6.725) 4(-3.25,-6.725) 5(-2.75,-6.725) 6(-2.25,-6.725) 7(-1.75,-6.725) 8(-1.25,-6.725) 9(-0.75,-6.725) 10(-0.25,-6.725) 11(0.25,-6.725) 12(0.75,-6.725) 13(1.25,-6.725) 14(1.75,-6.725) 15(2.25,-6.725) 16(2.75,-6.725) 17(3.25,-6.725) 18(3.75,-6.725) 19(4.25,-6.725) 20(4.75,-6.725) 41(4.75,6.725) 42(4.25,6.725) 43(3.75,6.725) 44(3.25,6.725) 45(2.75,6.725) 46(2.25,6.725) 47(1.75,6.725) 48(1.25,6.725) 49(0.75,6.725) 50(0.25,6.725) 51(-0.25,6.725) 52(-0.75,6.725) 53(-1.25,6.725) 54(-1.75,6.725) 55(-2.25,6.725) 56(-2.75,6.725) 57(-3.25,6.725) 58(-3.75,6.725) 59(-4.25,6.725) 60(-4.75,6.725)
  rect 1.65x0.3 smd mask+0.05: 21(6.725,-4.75) 22(6.725,-4.25) 23(6.725,-3.75) 24(6.725,-3.25) 25(6.725,-2.75) 26(6.725,-2.25) 27(6.725,-1.75) 28(6.725,-1.25) 29(6.725,-0.75) 30(6.725,-0.25) 31(6.725,0.25) 32(6.725,0.75) 33(6.725,1.25) 34(6.725,1.75) 35(6.725,2.25) 36(6.725,2.75) 37(6.725,3.25) 38(6.725,3.75) 39(6.725,4.25) 40(6.725,4.75) 61(-6.75,4.75) 62(-6.75,4.25) 63(-6.75,3.75) 64(-6.75,3.25) 65(-6.75,2.75) 66(-6.75,2.25) 67(-6.75,1.75) 68(-6.75,1.25) 69(-6.75,0.75) 70(-6.75,0.25) 71(-6.75,-0.25) 72(-6.75,-0.75) 73(-6.75,-1.25) 74(-6.75,-1.75) 75(-6.75,-2.25) 76(-6.75,-2.75) 77(-6.75,-3.25) 78(-6.75,-3.75) 79(-6.75,-4.25) 80(-6.75,-4.75)
  silkscreen extent -5.2,-5.27 -3.95,-4.03, body extent -12.5,-12.5 12.5,12.5, height 13.2
ICC_TQFN12_2X1P7_P040 [mm]
  rect 0.2x0.75 smd paste+0 mask+0.05: 1(-0.8,-0.675) 2(-0.4,-0.675) 3(0,-0.675) 4(0.4,-0.675) 5(0.8,-0.675) 7(0.8,0.675) 8(0.4,0.675) 9(0,0.675) 10(-0.4,0.675) 11(-0.8,0.675)
  rect 0.85x0.2 smd paste+0 mask+0.05: 6(0.775,0) 12(-0.775,0)
  silkscreen extent -1.02,-0.85 1.02,0.85, body extent -1,-0.85 1,0.85, height 0.56
ICC_UDFN6-EPAD_2X2_P065 [mm] "MCD-02159"
  rect 0.27x0.7 smd mask+0.05: 1(-0.65,-0.89) 2(0,-0.89) 3(0.65,-0.89) 4(0.65,0.89) 5(0,0.89) 6(-0.65,0.89)
  rect 1.45x0.65 smd mask+0.05: 7(0,0)
  silkscreen extent -1.15,-1.33 1.02,1.02, body extent -1.03,-1.03 1.02,1.02, height 0.56
ICC_VSSOP8_DCU_R-PDSO-G8_2X2P30_P050 [mm]
  rect 0.3x0.8 smd mask+0.05: 1(-0.75,-1.55) 2(-0.25,-1.55) 3(0.25,-1.55) 4(0.75,-1.55) 5(0.75,1.55) 6(0.25,1.55) 7(-0.25,1.55) 8(-0.75,1.55)
  silkscreen extent -1.05,-1.2 1.05,1.2, body extent -1.05,-1.62 1.05,1.62, height 0.9
ICC_WLCSP12_1P858x1P318_P040 [mm] "MCD-03166"
  round 0.215 smd paste+0 mask+0.04: A1(-0.6,0.4) A2(-0.2,0.4) A3(0.2,0.4) A4(0.6,0.4) B1(-0.6,0) B2(-0.2,0) B3(0.2,0) B4(0.6,0) C1(-0.6,-0.4) C2(-0.2,-0.4) C3(0.2,-0.4) C4(0.6,-0.4)
  silkscreen extent -1.07,-0.66 0.93,0.8, body extent -0.93,-0.66 0.93,0.66, height 0.62
IND_TDK_VLS252010HBX-1 [mm]
  rect 0.6x2 smd mask+0.05: 1(-0.95,0) 2(0.95,0)
  silkscreen extent -1.38,-1.12 1.38,1.12, body extent -1.35,-1.1 1.35,1.1, height 1.01
LCD_DISPLAY_GH08172_DIP28 [mm] "MCD-03134"
  rect 1.4x1.4 / inner round 1.4 / far side rect 1.4x1.4 hole 1 mask+0.05: 1(-16.51,-7.62)
  round 1.4 hole 1 mask+0.05: 2(-13.97,-7.62) 3(-11.43,-7.62) 4(-8.89,-7.62) 5(-6.35,-7.62) 6(-3.81,-7.62) 7(-1.27,-7.62) 8(1.27,-7.62) 9(3.81,-7.62) 10(6.35,-7.62) 11(8.89,-7.62) 12(11.43,-7.62) 13(13.97,-7.62) 14(16.51,-7.62) 15(16.51,7.62) 16(13.97,7.62) 17(11.43,7.62) 18(8.89,7.62) 19(6.35,7.62) 20(3.81,7.62) 21(1.27,7.62) 22(-1.27,7.62) 23(-3.81,7.62) 24(-6.35,7.62) 25(-8.89,7.62) 26(-11.43,7.62) 27(-13.97,7.62) 28(-16.51,7.62)
  silkscreen extent -18.38,-7.72 18.38,7.72, body extent -18.38,-7.72 18.38,7.72, height 2.9
"LED_0402_EVERLIGHT_16-213SYGC/S530-E3-TR8 _YELLOW-GREEN_1A2K_H0P45" [mm] "MCD-02330"
  rect 0.6x0.7 smd mask+0.05: 1(0.55,0) 2(-0.55,0)
  silkscreen extent -0.97,-0.3 0.13,0.3, body extent -0.55,-0.3 0.55,0.3, height 0.55
LED_0402_KINGBRIGHT_KPHHS-1005QBC-D-V_BLUE_1A2K_H0P5 [mm] "MCD-00706"
  rect 0.7x0.5 smd mask+0.05: 1(-0.55,0) 2(0.55,0)
  silkscreen extent -0.5,-0.38 1,0.38, body extent -0.5,-0.3 0.51,0.3, height 0.6
LED_0402_KINGBRIGHT_KPHHS-1005SURCK_HYPER-RED_1A2K_H0P5 [mm] "MCD-00708"
  rect 0.7x0.5 smd mask+0.05: 1(-0.55,0) 2(0.55,0)
  silkscreen extent -0.5,-0.38 1,0.38, body extent -0.5,-0.3 0.51,0.3, height 0.6
LED_BI-GR_WE-150141SV73110 [mm] "MCD-02631"
  rect 1.1x1.5 smd mask+0.05: 1(-0.75,1.5) 2(0.75,1.5) 3(-0.75,-1.5) 4(0.75,-1.5)
  silkscreen extent -1.65,-1.85 1.5,1.7, body extent -1.5,-1.85 1.5,1.85, height 2.1
MIRE_PLACE_SMD_1MM [mm]
  round 1 smd paste-10 mask+1: 1(0,0)
  Top Layer keep-out circle w0.01: c0,0 r1.5
MOS_SOT23-5L [mm]
  rect 0.6x1.3 smd mask+0.05: 1(-0.95,-1.1) 2(0,-1.1) 3(0.95,-1.1) 4(0.95,1.1) 5(-0.95,1.1)
  silkscreen extent -1.6,-0.95 1.6,0.97, body extent -1.52,-1.25 1.52,1.25, height 1.45
NPN_SOT23 [mm]
  rect 1x1.4 smd mask+0.05: 1(-0.95,-1.1) 2(0.95,-1.1) 3(0,1.1)
  silkscreen extent -1.63,-0.82 1.63,0.82, body extent -1.56,-1.25 1.56,1.25, height 1.1
R0402 [mm]
  rect 0.51x0.7 smd mask+0.05: 1(-0.45,0) 2(0.45,0)
  body extent -0.52,-0.3 0.52,0.3, height 0.4
R0603 [mm]
  rect 0.64x1 smd mask+0.05: 1(-0.7,0) 2(0.7,0)
  silkscreen extent -1.05,-0.58 1.05,0.58, body extent -0.9,-0.5 0.9,0.5, height 0.56
REG_SOT23-5L [mm]
  rect 0.6x1.3 smd mask+0.05: 1(-0.95,-1.1) 2(0,-1.1) 3(0.95,-1.1) 4(0.95,1.1) 5(-0.95,1.1)
  silkscreen extent -1.6,-0.95 1.6,0.97, body extent -1.52,-1.25 1.52,1.25, height 1.1
REG_SOT223-TAB [mm]
  rect 1.5x1.65 smd mask+0.05: 1(-2.3,-3.175) 2(0,-3.175) 3(2.3,-3.175)
  rect 3.5x1.65 smd mask+0.05: 4(0,3.175)
  silkscreen extent -3.35,-2.15 3.35,2.12, body extent -3.35,-3.48 3.35,3.48, height 1.8
SOLDER-BRIDGE_R0603-0R [mil]
  round 10 smd paste-393.7: 1(-19.69,0) 2(23.62,0)
  Top Layer region: -47.24,-19.69 -47.24,19.68 -15.75,19.68 3.94,0 -15.75,-19.69 -47.24,-19.69
  Top Layer region: -5.91,19.68 13.78,0 -5.91,-19.69 47.24,-19.69 47.24,19.68 -5.91,19.68
  silkscreen extent -50,-23 50,23, body extent -36,-20 36,20, height 22
STICKER_BOARD_25X9 [mil] "Sticker to mention board CPN code"
  silkscreen extent -492,-177 492,177
STICKER_PRODUCT_25X9 [mil] "Sticker to mention board CPN code"
  silkscreen extent -492,-177 492,177
SWI_C&K_Y78B23110FP__ITT_KMR231GLFS [mm] "MCD-00715"
  rect 0.9x1 smd mask+0.05: 1(2.05,0.8) 2(2.05,-0.8) 3(-2.05,0.8) 4(-2.05,-0.8)
  rect 1.7x0.8 smd mask+0.05: 5(0,1.2)
  silkscreen extent -2.05,-1.43 2.05,1.43, body extent -2.3,-1.5 2.3,1.5, height 2.1
SWI_CTS_CTS218-4LP [mm] "GULL WING TERMINAL"
  rect 0.76x1.27 smd mask+0.05: 1(-1.905,-3.81) 2(-0.635,-3.81) 3(0.635,-3.81) 4(1.905,-3.81) 5(1.905,3.81) 6(0.635,3.81) 7(-0.635,3.81) 8(-1.905,3.81)
  silkscreen extent -3.13,-3.05 3.13,3.05, body extent -3.18,-4.32 3.18,4.32, height 2.85
SWI_XIEJIA_MT-008A_6P [mm] "MCD-00132"
  rect 1.8x1.1 smd mask+0.05: 1(-3.1,1.4) 2(-3.1,0) 3(-3.1,-1.4) 4(3.1,1.4) 5(3.1,0) 6(3.1,-1.4)
  rect 2.2x1.4 smd mask+0.05: 7(0,3.75) 8(0,-3.75)
  round 0 hole 0.8 unplated paste-10 mask+0.05: NPTH1(0,1.9)
  round 0 hole 1.1 unplated paste-10 mask+0.05: NPTH2(0,-1.9)
  silkscreen extent -3.7,-3.7 3.7,3.7, body extent -3.85,-3.75 3.85,3.75, height 5.2
TP_SMD_1MM [mm]
  round 1 smd paste-10 mask+0.05: 1(0,0)
  silkscreen extent -0.7,-0.7 0.7,0.7
TSB_TOUCH-SENSING-BUTTON_TS-PAD-10_SHIELD-14 [mm]
  round 0.1 smd paste-10 mask+0.05: SHIELD(-0.26,-7.25) SHIELD(0.26,-7.25)
  round 0.12 smd paste-10 mask+0.05: TKEY(0,-7.25)
  Top Layer region: 0,5 -1.913,4.619 -3.536,3.536 -4.619,1.913 -5,0 -5,0 0,0 -5,0 -4.619,-1.913 -3.536,-3.536 -1.913,-4.619 0,-5 0,-5 1.913,-4.619 3.536,-3.536 4.619,-1.913 5,0 5,0 4.619,1.913 3.536,3.536 1.913,4.619 0,5 0,5 0,0
  Top Layer lines w0.1: 0.26,-5.25 0.26,-7.25 ; -0.26,-5.25 -0.26,-7.25
  Top Layer lines w0.12: 0,0 0,-7.25
  silkscreen extent -7.12,-7.12 7.12,7.12, body extent -7,-7 7,7, height 4

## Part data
B1: library part MCD-01485, "Switch tactile, SPST-NO, 32V, 50mA, 2.8x4.6mm", Manufacturer=C&K, Manufacturer_Part_Number=KMR231GLFS, Package=2.8x4.6mm
B2: library part MCD-00132, "Joystick, Black hat", Manufacturer="XIEJIA ELECTRONICS", Manufacturer_Part_Number=MT-008A, Package=7.4x7.5mm
C1 C2 C6 C14 C15 C16 C17 C19 C22 C23 C29 C33 C34 C35 C40 C44 C46 C48 C49 C54 C55 C56 C57 C58: library part MCD-00006, "Capacitor, MLCC, 100nF, 16V, X7R, +/-10%, 0402, T=0.5mm", Manufacturer=YAGEO, Manufacturer_Part_Number=CC0402KRX7R7BB104, Package=0402
C3 C52: library part MCD-01099, "Capacitor, MLCC, 100nF, 50V, X7R, +/-10%, 0603, T=0.8mm", Manufacturer=YAGEO, Manufacturer_Part_Number=CC0603KRX7R9BB104, Package=0603
C4 C11 C24 C25 C26 C27 C51: library part MCD-00099, "Capacitor, MLCC, 10uF, 10V, X5R, +/-10%, 0603, T=0.8mm", Manufacturer=MURATA, Manufacturer_Part_Number=GRM188R61A106KE69D, Package=0603
C5 C53: library part MCD-00205, "Capacitor, MLCC, 100pF, 50V, NPO, +/-5%, 0402, T=0.5mm", Manufacturer=YAGEO, Manufacturer_Part_Number=CC0402JRNPO9BN101, Package=0402
C7 C8: library part MCD-00015, "Capacitor, MLCC, 10pF, 50V, NPO, +/-5%, 0402, T=0.5mm", Manufacturer=YAGEO, Manufacturer_Part_Number=CC0402JRNPO9BN100, Package=0402
C9: library part MCD-00016, "Capacitor, MLCC, 20pF, 50V, NPO, +/- 5%, 0402, T=0.5mm", Manufacturer=YAGEO, Manufacturer_Part_Number=CC0402JRNPO9BN200, Package=0402
C10 C18 C41: library part MCD-02198, "Capacitor, MLCC, 10nF, 50V, X7R, +/-10%, 0402, T=0.5mm", Manufacturer=YAGEO, Manufacturer_Part_Number=CC0402KRX7R9BB103, Package=0402
C12 C13 C20 C21 C43 C45 C47: library part MCD-00010, "Capacitor, MLCC, 1uF, 16V, X5R, +/-10%, 0603, T=0.8mm", Manufacturer=YAGEO, Manufacturer_Part_Number=CC0603KRX5R7BB105, Package=0603
C28: library part MCD-03332, "Capacitor, Electrolytic Low ESR, 470uF, 25V, 0R06, +/-20%, TH, Radial pitch 5mm, D=10mm, T=16mm", Manufacturer=TDK, Manufacturer_Part_Number=B41888C5477M000, Package=10x16mm
C30 C32: library part MCD-00014, "Capacitor, MLCC, 10uF, 25V, X5R, +/-10%, 0805, T=0.85mm", Manufacturer=YAGEO, Manufacturer_Part_Number=CC0805KRX5R8BB106, Package=0805
C31: library part MCD-01721, "Capacitor, MLCC, 4.7uF, 10V, X5R, +/-10%, 0603, T=0.8mm", Manufacturer=YAGEO, Manufacturer_Part_Number=CC0603KRX5R6BB475, Package=0603
C36 C37: library part MCD-01932, "Capacitor, MLCC, 8.2pF, 50V, NPO, +/-0.25pF, 0402, T=0.5mm", Manufacturer=YAGEO, Manufacturer_Part_Number=CC0402CRNPO9BN8R2, Package=0402
C38 C39: library part MCD-01374, "Capacitor, MLCC, 5.6pF, 50V, NPO, +/-0.1pF, 0402, T=0.5mm", Manufacturer=YAGEO, Manufacturer_Part_Number=CC0402BRNPO9BN5R6, Package=0402
C42: library part MCD-01939, "Capacitor, MLCC, 39nF, 50V, COG, +/-5%, 1206, T=0.85mm", Manufacturer=MURATA, Manufacturer_Part_Number=GRM3195C1H393JA01D, Package=1206
C50: library part MCD-02154, "Capacitor, MLCC, 390nF, 10V, X5R, +/-10%, 0402, T=0.5mm", Manufacturer=MURATA, Manufacturer_Part_Number=GMD155R61A394KE11J, Package=0402
CN1 CN14: library part MCD-03232, "USB_TypeC, 24 pins, RA, SMD, T=2.96mm", Manufacturer="AMPHENOL ICC", Manufacturer_Part_Number=12401826E412A
CN2: library part MCD-00031, "Header_Plug-of-nails, 5x2, 1.27mm, No legs", Manufacturer=N/A
CN3: library part MCD-00029, "Header, 4x1, 2.54mm, VR, TH, T=5.84mm/2.54mm", Manufacturer=SAMTEC, Manufacturer_Part_Number=TSW-104-07-G-S
CN4: library part MCD-01226, "Header, 5x2, 1.27mm, VR, SMD, T=5.97mm/3.05mm", Manufacturer=SAMTEC, Manufacturer_Part_Number=FTSH-105-01-L-DV-K
CN5: library part MCD-02080, "Socket, 10x1, 2.54mm, VR, TH, T=8.51/2.64mm", Manufacturer=SAMTEC, Manufacturer_Part_Number=SSW-110-01-G-S
CN6 CN9 CN12 CN13: library part MCD-01743, "Socket, 8x1, 2.54mm, VR, TH, T=8.51/2.64mm", Manufacturer=SAMTEC, Manufacturer_Part_Number=SSW-108-01-G-S
CN7 CN10: library part MCD-03295, "Header, 20x2, 2.54mm, VR, TH, T=5.84mm/10.16mm", Manufacturer=SAMTEC, Manufacturer_Part_Number=TSW-120-09-G-D
CN8: library part MCD-02079, "Socket, 6x1, 2.54mm, VR, TH, T=8.51/2.64mm", Manufacturer=SAMTEC, Manufacturer_Part_Number=SSW-106-01-G-S
CN11: library part MCD-00032, "Header, 2x1, 2.54mm, VR, TH, T=5.84mm/2.54mm", Manufacturer=SAMTEC, Manufacturer_Part_Number=TSW-102-07-G-S
D1 D2: library part MCD-00034, "Diode, Schottky, 0V53, 1A, 10V, SOD-323", Manufacturer=STMICROELECTRONICS, Manufacturer_HQ_COO=EU, Package=SOD323
HW1: library part MCD-00547, "Sticker product 25x9 mm", Manufacturer=N/A
HW2: library part MCD-00235, "Sticker Board 25x9 mm", Manufacturer=N/A
JP1 JP2: library part MCD-00214, "Header, 2x1, 2.54mm, VR, TH, T=5.84mm/10.16mm", Manufacturer=SAMTEC, Manufacturer_Part_Number=TSW-102-09-G-S
JP3: library part MCD-01203, "Header, 5x2, 2.54mm, VR, TH, T=5.84mm/2.54mm", Manufacturer=SAMTEC, Manufacturer_Part_Number=TSW-105-07-G-D
JP4: library part MCD-00045, "Header, 2x1, 2.54mm, VR, TH, T=5.84mm/2.54mm", Manufacturer=SAMTEC, Manufacturer_Part_Number=TSW-102-07-G-S
JP5 JP7: library part MCD-00683, "Header, 2x1, 2.54mm, VR, TH, T=5.84mm/2.54mm", Manufacturer=SAMTEC, Manufacturer_Part_Number=TSW-102-07-G-S
JP6: library part MCD-00684, "Header, 3x1, 2.54mm, VR, TH, T=5.84mm/2.54mm", Manufacturer=SAMTEC, Manufacturer_Part_Number=TSW-103-07-F-S
L1: library part MCD-00240, "Inductor, 2.2uH, +/-20%, 2.6A, 100mR, 2.5x2mm, T=1mm", Manufacturer=TDK, Manufacturer_Part_Number=VLS252010HBX-2R2M-1, Package=2.5x2mm
LD1: library part MCD-02631, "LED Bicolor, Green/Red, 2V, 20mA, 4-PLCC", Manufacturer="WURTH ELEKTRONIK", Manufacturer_Part_Number=150141SV73110, Package=4-PLCC
LD2 LD5: library part MCD-00708, "LED, Red, 1V95, 20mA, 0402", Manufacturer=KINGBRIGHT, Manufacturer_Part_Number=KPHHS-1005SURCK, Package=0402
LD3 LD6: library part MCD-02330, "LED Bicolor, Yellow/Green, 2V, 25mA, 0402", Manufacturer=EVERLIGHT, Manufacturer_Part_Number=16-213SYGC/S530-E3/TR8, Package=0402
LD4: library part MCD-00706, "LED, Blue, 3V3, 20mA, 0402", Manufacturer=KINGBRIGHT, Manufacturer_Part_Number=KPHHS-1005QBC-D-V, Package=0402
R1 R19 R26: library part MCD-00067, "Resistor, 100R, 0402, +/- 1%, 1/16W", Manufacturer=YAGEO, Manufacturer_Part_Number=RC0402FR-07100RL, Package=0402
R2 R20 R21 R31 R38 R46 R47 R50 R65 R72: library part MCD-00059, "Resistor, 100K, 0402, +/-1%, 1/16W", Manufacturer=YAGEO, Manufacturer_Part_Number=RC0402FR-07100KL, Package=0402
R3 R11 R12 R15 R24 R29 R56: library part MCD-00053, "Resistor, 10K, 0402, +/-1%, 1/16W", Manufacturer=YAGEO, Manufacturer_Part_Number=RC0402FR-0710KL, Package=0402
R4 R10 R16 R63 R64 R67: library part MCD-00333, "Resistor, 5K1, 0402, +/-1%, 1/16W", Manufacturer=YAGEO, Manufacturer_Part_Number=RC0402FR-075K1L, Package=0402
R5: library part MCD-00069, "Resistor, 36K, 0402, +/-1%, 1/16W", Manufacturer=YAGEO, Manufacturer_Part_Number=RC0402FR-0736KL, Package=0402
R6: library part MCD-00062, "Resistor, 330R, 0402, +/-1%, 1/16W", Manufacturer=YAGEO, Manufacturer_Part_Number=RC0402FR-07330RL, Package=0402
R7 R22 R51 R60: library part MCD-00061, "Resistor, 1K, 0402, +/-1%,1/16W", Manufacturer=YAGEO, Manufacturer_Part_Number=RC0402FR-071KL, Package=0402
R8: library part MCD-00068, "Resistor, 1K5, 0402, +/-1%, 1/16W", Manufacturer=YAGEO, Manufacturer_Part_Number=RC0402FR-071K5L, Package=0402
R9 R61: library part MCD-00413, "Resistor, 180K, 0402, +/-1%, 1/16W", Manufacturer=YAGEO, Manufacturer_Part_Number=RC0402FR-07180KL, Package=0402
R13 R62: library part MCD-00513, "Resistor, 680K, 0402, +/-1%, 1/16W", Manufacturer=YAGEO, Manufacturer_Part_Number=RC0402FR-07680KL, Package=0402
R14 R17 R27 R33 R34 R35: library part MCD-00455, "Resistor, 33R, 0402, +/-1%, 1/16W", Manufacturer=YAGEO, Manufacturer_Part_Number=RC0402FR-0733RL, Package=0402
R18 R23 R25 R28 R44 R52 R53 R54 R55 R58: library part MCD-00052, "Resistor, 0R, 0402, +/-5%, 1/16W", Manufacturer=YAGEO, Manufacturer_Part_Number=RC0402JR-070RL, Package=0402
R30 R37 R66 R73: library part MCD-00063, "Resistor, 47K, 0402, +/-1%, 1/16W", Manufacturer=YAGEO, Manufacturer_Part_Number=RC0402FR-0747KL, Package=0402
R32: library part MCD-00441, "Resistor, 270R, 0402, +/-1%, 1/16W", Manufacturer=YAGEO, Manufacturer_Part_Number=RC0402FR-07270RL, Package=0402
R36 R39: library part MCD-00461, "Resistor, 360R, 0402, +/-1%, 1/16W", Manufacturer=YAGEO, Manufacturer_Part_Number=RC0402FR-07360RL, Package=0402
R40 R41 R43 R45: library part MCD-00182, "Resistor, 1M, 0402, +/-1%, 1/16W", Manufacturer=YAGEO, Manufacturer_Part_Number=RC0402FR-071ML, Package=0402
R42: library part MCD-00507, "Resistor, 680R, 0402, +/-1%, 1/16W", Manufacturer=YAGEO, Manufacturer_Part_Number=RC0402FR-07680RL, Package=0402
R48 R49: library part MCD-00065, "Resistor, 4K7, 0402, +/-1%, 1/16W", Manufacturer=YAGEO, Manufacturer_Part_Number=RC0402FR-074K7L, Package=0402
R57: library part MCD-00419, "Resistor, 2K, 0402, +/-1%, 1/16W", Manufacturer=YAGEO, Manufacturer_Part_Number=RC0402FR-072KL, Package=0402
R59: library part MCD-00056, "Resistor, 0R, 0603, +/-5%, 1/10W", Manufacturer=YAGEO, Manufacturer_Part_Number=RC0603JR-070RL, Package=0603
R68: library part MCD-00409, "Resistor, 1K8, 0402, +/-1%, 1/16W", Manufacturer=YAGEO, Manufacturer_Part_Number=RC0402FR-071K8L, Package=0402
R69: library part MCD-00527, "Resistor, 820R, 0402, +/-1%, 1/16W", Manufacturer=YAGEO, Manufacturer_Part_Number=RC0402FR-07820RL, Package=0402
R70: library part MCD-00064, "Resistor, 510R, 0402, +/-1%, 1/16W", Manufacturer=YAGEO, Manufacturer_Part_Number=RC0402FR-07510RL, Package=0402
R71: library part MCD-00531, "Resistor, 82K, 0402, +/-1%, 1/16W", Manufacturer=YAGEO, Manufacturer_Part_Number=RC0402FR-0782KL, Package=0402
SB1 SB2 SB4 SB5 SB6 SB10 SB12 SB14 SB15 SB17 SB19 SB20 SB21 SB24: library part MCD-00071, "Resistor, 0R, SB0603, 5%, 0.1W", Manufacturer=YAGEO, Manufacturer_HQ_COO=Unknown, Manufacturer_Part_Number=RC0603JR-070RL, Package=0603
SB3 SB7 SB8 SB9 SB11 SB13 SB16 SB18 SB22 SB23: library part MCD-00072, "Resistor, 0R, SB0603, 5%, 0.1W", Manufacturer=YAGEO, Manufacturer_HQ_COO=Unknown, Manufacturer_Part_Number=RC0603JR-070RL, Package=0603
SW1: library part MCD-00167, "SMT half pitch DIP switch, SPST, 50V, 100mA, 6.6x6.25mm", Manufacturer=CTS, Manufacturer_Part_Number=218-4LPSTR, Package=6.6x6.25mm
